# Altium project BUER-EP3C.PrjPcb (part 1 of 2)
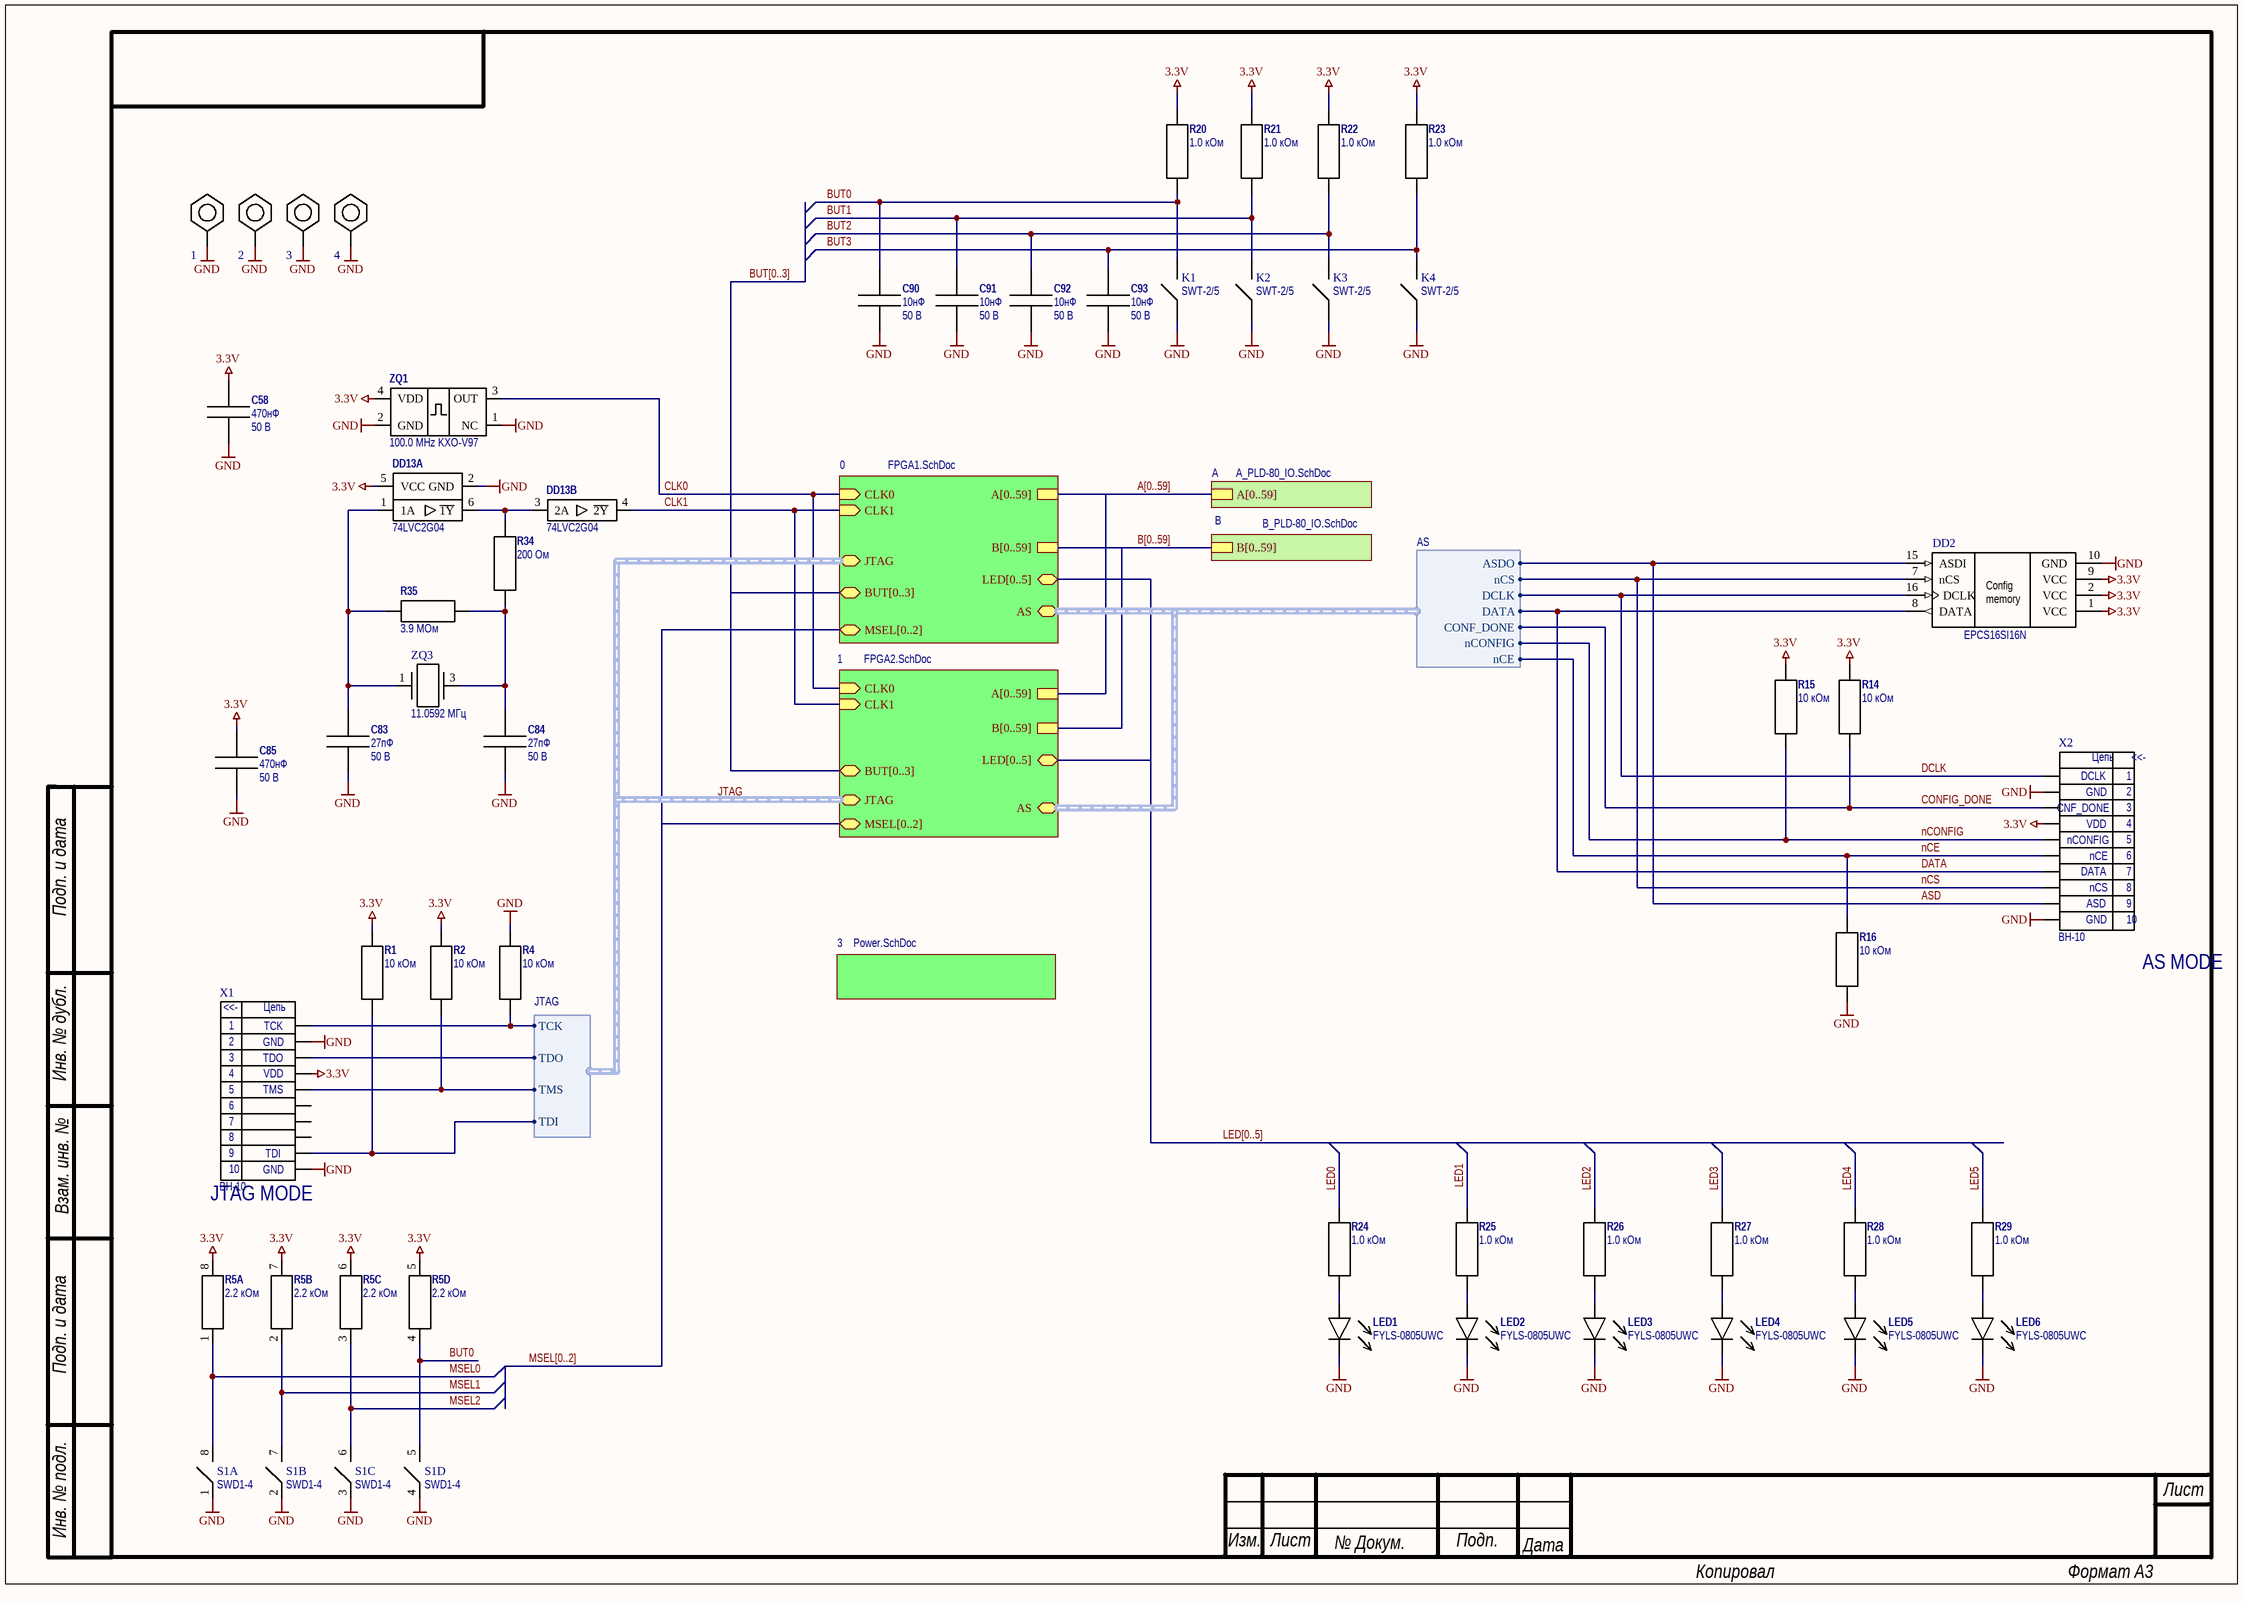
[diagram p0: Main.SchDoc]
Firma: Òåõíîèìïåêñ; Proveril: Êîñòåíêî Ì.Â; Razrabotal: Òîâñòîïÿò ß. À.; Utverdil: Áîãà÷åâ Î.Ã.
17 sheets, 295 parts. Net scope: hierarchical (ports join the sheet entries above them; power ports are global).
Board file: BUER_EP3C.PcbDoc
Sheets:
  Main.SchDoc
    0 = FPGA1.SchDoc
    3 = Power.SchDoc
      D = 5V_to_1.2V_stepdown.SchDoc
      G = 5V_to_2.5V_stepdown.SchDoc
      H = 5V_to_3.3V_stepdown.SchDoc
      S = 5A Stepdown 5V.SchDoc
      F = 5V_to_1.8V_stepdown.SchDoc
    1 = FPGA2.SchDoc
    A = A_PLD-80_IO.SchDoc
      1 = 10pin ESD protect_1.SchDoc
      2 = 10pin ESD protect_2.SchDoc
      3 = 10pin ESD protect_3.SchDoc
      4 = 10pin ESD protect_4.SchDoc
      6 = 10pin ESD protect_6.SchDoc
      5 = 10pin ESD protect_5.SchDoc
    B = B_PLD-80_IO.SchDoc
      1 = 10pin ESD protect_1.SchDoc
      2 = 10pin ESD protect_2.SchDoc
      3 = 10pin ESD protect_3.SchDoc
      4 = 10pin ESD protect_4.SchDoc
      6 = 10pin ESD protect_6.SchDoc
      5 = 10pin ESD protect_5.SchDoc

## Sheet Main.SchDoc
size custom portrait

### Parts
1  M3  [M3]  (value not drawn)
2  M3  [M3]  (value not drawn)
3  M3  [M3]  (value not drawn)
4  M3  [M3]  (value not drawn)
C58  value 470нФ  VOLTAGE: 50 В  [C0805]  (hidden comment: 470нФ 10% 50 В)
C83  value 27пФ  VOLTAGE: 50 В  [C0805]  (hidden comment: 27пФ  5%  50В 0805 NPO)
C84  value 27пФ  VOLTAGE: 50 В  [C0805]  (hidden comment: 27пФ  5%  50В 0805 NPO)
C85  value 470нФ  VOLTAGE: 50 В  [C0805]  (hidden comment: 470нФ 10% 50 В)
C90  value 10нФ  VOLTAGE: 50 В  [C0805]  (hidden comment: 10нФ 10% 50 В)
C91  value 10нФ  VOLTAGE: 50 В  [C0805]  (hidden comment: 10нФ 10% 50 В)
C92  value 10нФ  VOLTAGE: 50 В  [C0805]  (hidden comment: 10нФ 10% 50 В)
C93  value 10нФ  VOLTAGE: 50 В  [C0805]  (hidden comment: 10нФ 10% 50 В)
DD2  EPCS16SI16N  [SO-16W]
DD13  74LVC2G04  [SOT-23-6]  (parts A,B of 2)
K1  SWT-2/5 (0650HIM-160G-G)  [SWT-2/5]  (value not drawn)
K2  SWT-2/5 (0650HIM-160G-G)  [SWT-2/5]  (value not drawn)
K3  SWT-2/5 (0650HIM-160G-G)  [SWT-2/5]  (value not drawn)
K4  SWT-2/5 (0650HIM-160G-G)  [SWT-2/5]  (value not drawn)
LED1  FYLS-0805UWC  [LED0805W]
LED2  FYLS-0805UWC  [LED0805W]
LED3  FYLS-0805UWC  [LED0805W]
LED4  FYLS-0805UWC  [LED0805W]
LED5  FYLS-0805UWC  [LED0805W]
LED6  FYLS-0805UWC  [LED0805W]
R1  value 10 кОм  [R0603]  (hidden comment: 10 кОм 0603 5%)
R2  value 10 кОм  [R0603]  (hidden comment: 10 кОм 0603 5%)
R4  value 10 кОм  [R0603]  (hidden comment: 10 кОм 0603 5%)
R5  value 2.2 кОм  [4D03]  (hidden comment: 2.2 кОм 4D03)  (parts A,B,C,D of 4)
R14  value 10 кОм  [R0603]  (hidden comment: 10 кОм 0603 5%)
R15  value 10 кОм  [R0603]  (hidden comment: 10 кОм 0603 5%)
R16  value 10 кОм  [R0603]  (hidden comment: 10 кОм 0603 5%)
R20  value 1.0 кОм  [R0603]  (hidden comment: 1.0 кОм 0603 5%)
R21  value 1.0 кОм  [R0603]  (hidden comment: 1.0 кОм 0603 5%)
R22  value 1.0 кОм  [R0603]  (hidden comment: 1.0 кОм 0603 5%)
R23  value 1.0 кОм  [R0603]  (hidden comment: 1.0 кОм 0603 5%)
R24  value 1.0 кОм  [R0603]  (hidden comment: 1.0 кОм 0603 5%)
R25  value 1.0 кОм  [R0603]  (hidden comment: 1.0 кОм 0603 5%)
R26  value 1.0 кОм  [R0603]  (hidden comment: 1.0 кОм 0603 5%)
R27  value 1.0 кОм  [R0603]  (hidden comment: 1.0 кОм 0603 5%)
R28  value 1.0 кОм  [R0603]  (hidden comment: 1.0 кОм 0603 5%)
R29  value 1.0 кОм  [R0603]  (hidden comment: 1.0 кОм 0603 5%)
R34  value 200 Ом  [R0805]  (hidden comment: 200 Ом 0805 5%)
R35  value 3.9 МОм  [R0805]  (hidden comment: 3.9 МОм 0805 5%)
S1  SWD1-4  [DIPSW-4]  (parts A,B,C,D of 4)
X1  BH-10  [BH-10]
X2  BH-10  [BH-10]
ZQ1  100.0 MHz KXO-V97  [KXO-97]
ZQ3  FREQUENCY: 11.0592 МГц  [KX-9A]  (hidden comment: 11.0592MHz KX-9A)

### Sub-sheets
0 = FPGA1.SchDoc: CLK0 (in), CLK1 (in), A[0..59], B[0..59], AS (harness AS), JTAG (harness JTAG), MSEL[0..2], BUT[0..3], LED[0..5]
1 = FPGA2.SchDoc: CLK0 (in), CLK1 (in), MSEL[0..2], JTAG (harness JTAG), AS (harness AS), A[0..59], B[0..59], BUT[0..3], LED[0..5]
3 = Power.SchDoc: no entries
A = A_PLD-80_IO.SchDoc: A[0..59]
B = B_PLD-80_IO.SchDoc: B[0..59]

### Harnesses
JTAG: TCK, TDO, TMS, TDI
AS: nCE, DCLK, CONF_DONE, nCONFIG, ASDO, nCS, DATA

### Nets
3.3V: C58.1 C85.1 DD2.1(VCC) DD2.2(VCC) DD2.9(VCC) DD13.5(VCC) R1.2 R2.2 R5.5 R5.6 R5.7 R5.8 R14.2 R15.2 R20.2 R21.2 R22.2 R23.2 X1.4 X2.4 ZQ1.4(VDD)
GND: 1.0 2.0 3.0 4.0 C58.2 C83.2 C84.2 C85.2 C90.2 C91.2 C92.2 C93.2 DD2.10(GND) DD13.2(GND) K1.1 K2.1 K3.1 K4.1 LED1.K LED2.K LED3.K LED4.K LED5.K LED6.K R4.2 R16.1 S1.1 S1.2 S1.3 S1.4 X1.2 X1.10 X2.2 X2.10 ZQ1.1(NC) ZQ1.2(GND)
ASD: DD2.15(ASDI) X2.9 ; sheet 0/AS.ASDO
BUT0: C90.1 K1.2 R5.4 R20.1 S1.5
BUT1: C91.1 K2.2 R21.1
BUT2: C92.1 K3.2 R22.1
BUT3: C93.1 K4.2 R23.1
CLK0: ZQ1.3(OUT) ; sheet 0/CLK0, sheet 1/CLK0
CLK1: DD13.4(~{2Y}) ; sheet 0/CLK1, sheet 1/CLK1
CONFIG_DONE: R14.1 X2.3 ; sheet 0/AS.CONF_DONE
DATA: DD2.8(DATA) X2.7 ; sheet 0/AS.DATA
DCLK: DD2.16(DCLK) X2.1 ; sheet 0/AS.DCLK
JTAG.TCK: R4.1 X1.1 ; sheet 0/JTAG.TCK
JTAG.TDI: R1.1 X1.9 ; sheet 0/JTAG.TDI
JTAG.TDO: X1.3 ; sheet 0/JTAG.TDO
JTAG.TMS: R2.1 X1.5 ; sheet 0/JTAG.TMS
LED0: R24.2
LED1: R25.2
LED2: R26.2
LED3: R27.2
LED4: R28.2
LED5: R29.2
MSEL0: R5.1 S1.8
MSEL1: R5.2 S1.7
MSEL2: R5.3 S1.6
nCE: R16.2 X2.6 ; sheet 0/AS.nCE
nCONFIG: R15.1 X2.5 ; sheet 0/AS.nCONFIG
nCS: DD2.7(nCS) X2.8 ; sheet 0/AS.nCS
NetC83_1: C83.1 DD13.1(1A) R35.1 ZQ3.1
NetC84_1: C84.1 R34.1 R35.2 ZQ3.3
NetDD13_3: DD13.3(2A) DD13.6(~{1Y}) R34.2
NetLED1_A: LED1.A R24.1
NetLED2_A: LED2.A R25.1
NetLED3_A: LED3.A R26.1
NetLED4_A: LED4.A R27.1
NetLED5_A: LED5.A R28.1
NetLED6_A: LED6.A R29.1

Not connected (* = marked no-connect by the designer): X1 6 7 8

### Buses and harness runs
bus A[0..59] = sheet 0/A[0..59] = sheet 1/A[0..59] = sheet A/A[0..59]
bus B[0..59] = sheet 0/B[0..59] = sheet 1/B[0..59] = sheet B/B[0..59]
bus BUT[0..3] = sheet 0/BUT[0..3] = sheet 1/BUT[0..3]
bus LED[0..5] = sheet 0/LED[0..5] = sheet 1/LED[0..5]
bus MSEL[0..2] = sheet 0/MSEL[0..2] = sheet 1/MSEL[0..2]
harness JTAG = sheet 0/JTAG = sheet 1/JTAG
harness sheet 0/AS = sheet 1/AS

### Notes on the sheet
- (near X2) DCLK
- (near X2) GND
- (near X2) CNF_DONE
- (near X2) nCONFIG
- (near X2) DATA
- (near X2) VDD
- (near X2) nCE
- Подп. и дата
- (near X2) ASD
- (near X2) nCS
- (near X2) AS MODE
- (near X1) TCK
- (near X1) TDO
- (near X1) GND
- (near X1) VDD
- Инв. № дубл.
- (near X1) TMS
- (near X1) JTAG MODE
- (near X1) TDI
- Взам. инв. №
- Инв. № подл.
- Лист
- Изм.
- № Докум.
- Подп.
- Дата
- Копировал
- Формат
- А3

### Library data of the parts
C58 C85 = 470нФ 50 В: конденсатор керамический SMD; Library Reference: capacitor; articul: 389
C83 C84 = 27пФ  50В: конденсатор керамический; Library Reference: capacitor; articul: 392
C90-C93 = 10нФ 50 В: конденсатор керамический SMD; articul: 398; Designator: capacitor
DD2 = EPCS16SI16N: EPCS16 Series, In-system programmable 3.3V serial configuration device, 8-Pin SOIC, 4-Megabit, Industrial Grade
DD13 = 74LVC2G04: 2-х разрядный инвертор
K1-K4 = SWT-2/5: тактовая кнопка
LED1-LED6 = FYLS-0805UWC: белый светодиод; articul: 701
R1 R2 R4 R14-R16 = 10 кОм 0603 5%: резистор постоянный; articul: 918
R5 = 2.2 кОм 4D03: Массив резисторов; Library Reference: 4X; articul: 138
R20-R29 = 1.0 кОм 0603 5%: резистор постоянный; articul: 720
R34 = 200 Ом 0805 5%: резистор постоянный; articul: 91
R35 = 3.9 МОм 0805 5%: резистор постоянный; articul: 86
S1 = SWD1-4: DIP переключатель на 4 позиции; articul: 140
X1 X2 = BH-10: вилка IDC на плату прямая; articul: 37
ZQ1 = 100.0 MHz KXO-V97: Кварцевый генератор
ZQ3 = 11.0592MHz KX-9A: Кварцевый резонатор; articul: 263

## Sheet FPGA1.SchDoc
size custom portrait
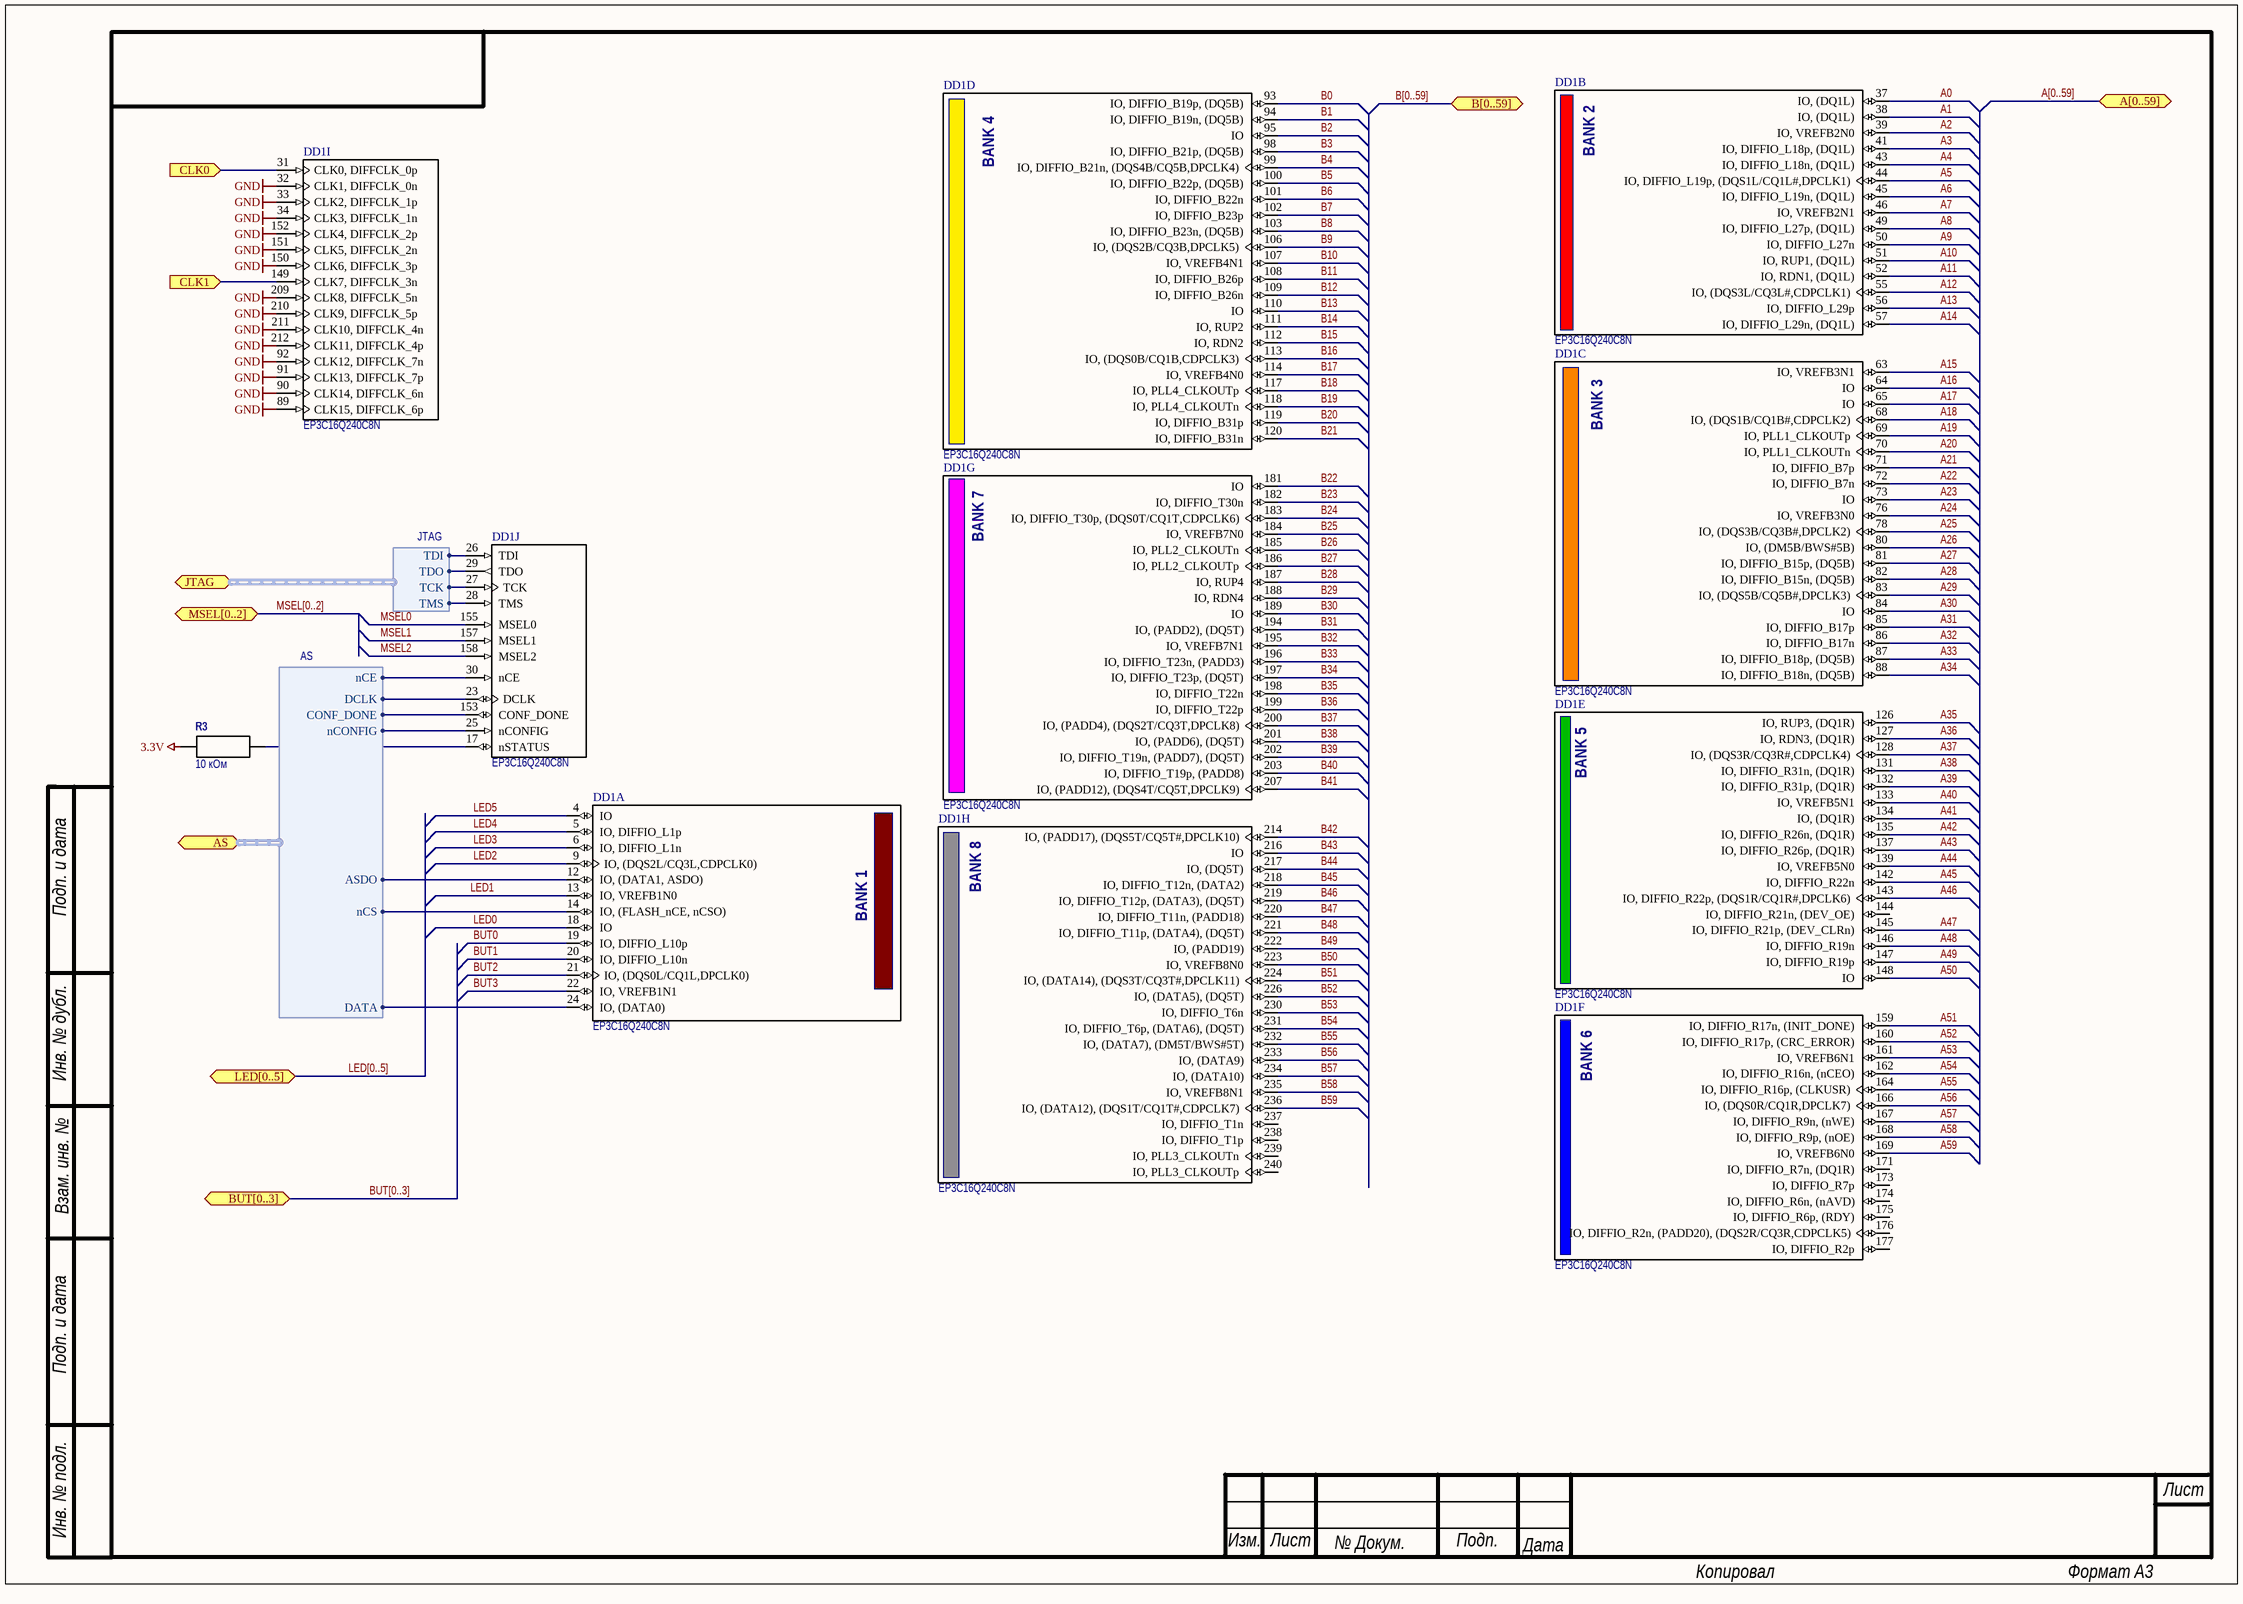
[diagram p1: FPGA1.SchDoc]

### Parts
DD1  EP3C16Q240C8N  [PQFP240_N]  (parts A,B,C,D,E,F,G,H,I,J of 13)
R3  value 10 кОм  [R0603]  (hidden comment: 10 кОм 0603 5%)

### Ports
A[0..59], AS (harness AS), B[0..59], BUT[0..3], CLK0 (in), CLK1 (in), JTAG (harness JTAG), LED[0..5], MSEL[0..2]

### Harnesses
JTAG: TCK, TDO, TMS, TDI
AS: nCE, DCLK, CONF_DONE, nCONFIG, ASDO, nCS, DATA

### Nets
3.3V: R3.2
GND: DD1.32(CLK1,_DIFFCLK_0n) DD1.33(CLK2,_DIFFCLK_1p) DD1.34(CLK3,_DIFFCLK_1n) DD1.89(CLK15,_DIFFCLK_6p) DD1.90(CLK14,_DIFFCLK_6n) DD1.91(CLK13,_DIFFCLK_7p) DD1.92(CLK12,_DIFFCLK_7n) DD1.150(CLK6,_DIFFCLK_3p) DD1.151(CLK5,_DIFFCLK_2n) DD1.152(CLK4,_DIFFCLK_2p) DD1.209(CLK8,_DIFFCLK_5n) DD1.210(CLK9,_DIFFCLK_5p) DD1.211(CLK10,_DIFFCLK_4n) DD1.212(CLK11,_DIFFCLK_4p)
A0: DD1.37(IO,_(DQ1L))
A1: DD1.38(IO,_(DQ1L))
A2: DD1.39(IO,_VREFB2N0)
A3: DD1.41(IO,_DIFFIO_L18p,_(DQ1L))
A4: DD1.43(IO,_DIFFIO_L18n,_(DQ1L))
A5: DD1.44(IO,_DIFFIO_L19p,_(DQS1L/CQ1L#,DPCLK1))
A6: DD1.45(IO,_DIFFIO_L19n,_(DQ1L))
A7: DD1.46(IO,_VREFB2N1)
A8: DD1.49(IO,_DIFFIO_L27p,_(DQ1L))
A9: DD1.50(IO,_DIFFIO_L27n)
A10: DD1.51(IO,_RUP1,_(DQ1L))
A11: DD1.52(IO,_RDN1,_(DQ1L))
A12: DD1.55(IO,_(DQS3L/CQ3L#,CDPCLK1))
A13: DD1.56(IO,_DIFFIO_L29p)
A14: DD1.57(IO,_DIFFIO_L29n,_(DQ1L))
A15: DD1.63(IO,_VREFB3N1)
A16: DD1.64(IO)
A17: DD1.65(IO)
A18: DD1.68(IO,_(DQS1B/CQ1B#,CDPCLK2))
A19: DD1.69(IO,_PLL1_CLKOUTp)
A20: DD1.70(IO,_PLL1_CLKOUTn)
A21: DD1.71(IO,_DIFFIO_B7p)
A22: DD1.72(IO,_DIFFIO_B7n)
A23: DD1.73(IO)
A24: DD1.76(IO,_VREFB3N0)
A25: DD1.78(IO,_(DQS3B/CQ3B#,DPCLK2))
A26: DD1.80(IO,_(DM5B/BWS#5B))
A27: DD1.81(IO,_DIFFIO_B15p,_(DQ5B))
A28: DD1.82(IO,_DIFFIO_B15n,_(DQ5B))
A29: DD1.83(IO,_(DQS5B/CQ5B#,DPCLK3))
A30: DD1.84(IO)
A31: DD1.85(IO,_DIFFIO_B17p)
A32: DD1.86(IO,_DIFFIO_B17n)
A33: DD1.87(IO,_DIFFIO_B18p,_(DQ5B))
A34: DD1.88(IO,_DIFFIO_B18n,_(DQ5B))
A35: DD1.126(IO,_RUP3,_(DQ1R))
A36: DD1.127(IO,_RDN3,_(DQ1R))
A37: DD1.128(IO,_(DQS3R/CQ3R#,CDPCLK4))
A38: DD1.131(IO,_DIFFIO_R31n,_(DQ1R))
A39: DD1.132(IO,_DIFFIO_R31p,_(DQ1R))
A40: DD1.133(IO,_VREFB5N1)
A41: DD1.134(IO,_(DQ1R))
A42: DD1.135(IO,_DIFFIO_R26n,_(DQ1R))
A43: DD1.137(IO,_DIFFIO_R26p,_(DQ1R))
A44: DD1.139(IO,_VREFB5N0)
A45: DD1.142(IO,_DIFFIO_R22n)
A46: DD1.143(IO,_DIFFIO_R22p,_(DQS1R/CQ1R#,DPCLK6))
A47: DD1.145(IO,_DIFFIO_R21p,_(DEV_CLRn))
A48: DD1.146(IO,_DIFFIO_R19n)
A49: DD1.147(IO,_DIFFIO_R19p)
A50: DD1.148(IO)
A51: DD1.159(IO,_DIFFIO_R17n,_(INIT_DONE))
A52: DD1.160(IO,_DIFFIO_R17p,_(CRC_ERROR))
A53: DD1.161(IO,_VREFB6N1)
A54: DD1.162(IO,_DIFFIO_R16n,_(nCEO))
A55: DD1.164(IO,_DIFFIO_R16p,_(CLKUSR))
A56: DD1.166(IO,_(DQS0R/CQ1R,DPCLK7))
A57: DD1.167(IO,_DIFFIO_R9n,_(nWE))
A58: DD1.168(IO,_DIFFIO_R9p,_(nOE))
A59: DD1.169(IO,_VREFB6N0)
ASD: DD1.12(IO,_(DATA1,_ASDO)) ; port AS.ASDO
B0: DD1.93(IO,_DIFFIO_B19p,_(DQ5B))
B1: DD1.94(IO,_DIFFIO_B19n,_(DQ5B))
B2: DD1.95(IO)
B3: DD1.98(IO,_DIFFIO_B21p,_(DQ5B))
B4: DD1.99(IO,_DIFFIO_B21n,_(DQS4B/CQ5B,DPCLK4))
B5: DD1.100(IO,_DIFFIO_B22p,_(DQ5B))
B6: DD1.101(IO,_DIFFIO_B22n)
B7: DD1.102(IO,_DIFFIO_B23p)
B8: DD1.103(IO,_DIFFIO_B23n,_(DQ5B))
B9: DD1.106(IO,_(DQS2B/CQ3B,DPCLK5))
B10: DD1.107(IO,_VREFB4N1)
B11: DD1.108(IO,_DIFFIO_B26p)
B12: DD1.109(IO,_DIFFIO_B26n)
B13: DD1.110(IO)
B14: DD1.111(IO,_RUP2)
B15: DD1.112(IO,_RDN2)
B16: DD1.113(IO,_(DQS0B/CQ1B,CDPCLK3))
B17: DD1.114(IO,_VREFB4N0)
B18: DD1.117(IO,_PLL4_CLKOUTp)
B19: DD1.118(IO,_PLL4_CLKOUTn)
B20: DD1.119(IO,_DIFFIO_B31p)
B21: DD1.120(IO,_DIFFIO_B31n)
B22: DD1.181(IO)
B23: DD1.182(IO,_DIFFIO_T30n)
B24: DD1.183(IO,_DIFFIO_T30p,_(DQS0T/CQ1T,CDPCLK6))
B25: DD1.184(IO,_VREFB7N0)
B26: DD1.185(IO,_PLL2_CLKOUTn)
B27: DD1.186(IO,_PLL2_CLKOUTp)
B28: DD1.187(IO,_RUP4)
B29: DD1.188(IO,_RDN4)
B30: DD1.189(IO)
B31: DD1.194(IO,_(PADD2),_(DQ5T))
B32: DD1.195(IO,_VREFB7N1)
B33: DD1.196(IO,_DIFFIO_T23n,_(PADD3))
B34: DD1.197(IO,_DIFFIO_T23p,_(DQ5T))
B35: DD1.198(IO,_DIFFIO_T22n)
B36: DD1.199(IO,_DIFFIO_T22p)
B37: DD1.200(IO,_(PADD4),_(DQS2T/CQ3T,DPCLK8))
B38: DD1.201(IO,_(PADD6),_(DQ5T))
B39: DD1.202(IO,_DIFFIO_T19n,_(PADD7),_(DQ5T))
B40: DD1.203(IO,_DIFFIO_T19p,_(PADD8))
B41: DD1.207(IO,_(PADD12),_(DQS4T/CQ5T,DPCLK9))
B42: DD1.214(IO,_(PADD17),_(DQS5T/CQ5T#,DPCLK10))
B43: DD1.216(IO)
B44: DD1.217(IO,_(DQ5T))
B45: DD1.218(IO,_DIFFIO_T12n,_(DATA2))
B46: DD1.219(IO,_DIFFIO_T12p,_(DATA3),_(DQ5T))
B47: DD1.220(IO,_DIFFIO_T11n,_(PADD18))
B48: DD1.221(IO,_DIFFIO_T11p,_(DATA4),_(DQ5T))
B49: DD1.222(IO,_(PADD19))
B50: DD1.223(IO,_VREFB8N0)
B51: DD1.224(IO,_(DATA14),_(DQS3T/CQ3T#,DPCLK11))
B52: DD1.226(IO,_(DATA5),_(DQ5T))
B53: DD1.230(IO,_DIFFIO_T6n)
B54: DD1.231(IO,_DIFFIO_T6p,_(DATA6),_(DQ5T))
B55: DD1.232(IO,_(DATA7),_(DM5T/BWS#5T))
B56: DD1.233(IO,_(DATA9))
B57: DD1.234(IO,_(DATA10))
B58: DD1.235(IO,_VREFB8N1)
B59: DD1.236(IO,_(DATA12),_(DQS1T/CQ1T#,CDPCLK7))
BUT0: DD1.19(IO,_DIFFIO_L10p)
BUT1: DD1.20(IO,_DIFFIO_L10n)
BUT2: DD1.21(IO,_(DQS0L/CQ1L,DPCLK0))
BUT3: DD1.22(IO,_VREFB1N1)
CLK0: DD1.31(CLK0,_DIFFCLK_0p) ; port CLK0
CLK1: DD1.149(CLK7,_DIFFCLK_3n) ; port CLK1
CONFIG_DONE: DD1.153(CONF_DONE) ; port AS.CONF_DONE
DATA: DD1.24(IO,_(DATA0)) ; port AS.DATA
DCLK: DD1.23(DCLK) ; port AS.DCLK
JTAG.TCK: DD1.27(TCK) ; port JTAG.TCK
JTAG.TDI: DD1.26(TDI) ; port JTAG.TDI
JTAG.TDO: DD1.29(TDO) ; port JTAG.TDO
JTAG.TMS: DD1.28(TMS) ; port JTAG.TMS
LED0: DD1.18(IO)
LED1: DD1.13(IO,_VREFB1N0)
LED2: DD1.9(IO,_(DQS2L/CQ3L,CDPCLK0))
LED3: DD1.6(IO,_DIFFIO_L1n)
LED4: DD1.5(IO,_DIFFIO_L1p)
LED5: DD1.4(IO)
MSEL0: DD1.155(MSEL0)
MSEL1: DD1.157(MSEL1)
MSEL2: DD1.158(MSEL2)
nCE: DD1.30(nCE) ; port AS.nCE
nCONFIG: DD1.25(nCONFIG) ; port AS.nCONFIG
nCS: DD1.14(IO,_(FLASH_nCE,_nCSO)) ; port AS.nCS
NetDD1_17: DD1.17(nSTATUS) R3.1

Not connected (* = marked no-connect by the designer): DD1 144(IO,_DIFFIO_R21n,_(DEV_OE)) 171(IO,_DIFFIO_R7n,_(DQ1R)) 173(IO,_DIFFIO_R7p) 174(IO,_DIFFIO_R6n,_(nAVD)) 175(IO,_DIFFIO_R6p,_(RDY)) 176(IO,_DIFFIO_R2n,_(PADD20),_(DQS2R/CQ3R,CDPCLK5)) 177(IO,_DIFFIO_R2p) 237(IO,_DIFFIO_T1n) 238(IO,_DIFFIO_T1p) 239(IO,_PLL3_CLKOUTn) 240(IO,_PLL3_CLKOUTp)

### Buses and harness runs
bus A[0..59] = port A[0..59]
bus B[0..59] = port B[0..59]
bus BUT[0..3] = port BUT[0..3]
bus LED[0..5] = port LED[0..5]
bus MSEL[0..2] = port MSEL[0..2]

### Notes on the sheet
- Подп. и дата
- Инв. № дубл.
- Взам. инв. №
- Инв. № подл.
- Лист
- Изм.
- № Докум.
- Подп.
- Дата
- Копировал
- Формат
- А3

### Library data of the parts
DD1 = EP3C16Q240C8N: Cyclone III Family FPGA, 160 I/O Pins, 4 PLLs, 240-Pin PQFP, Speed Grade 8, Commercial Grade, Pb-Free
R3 = 10 кОм 0603 5%: резистор постоянный; articul: 918

## Sheet Power.SchDoc
size custom portrait
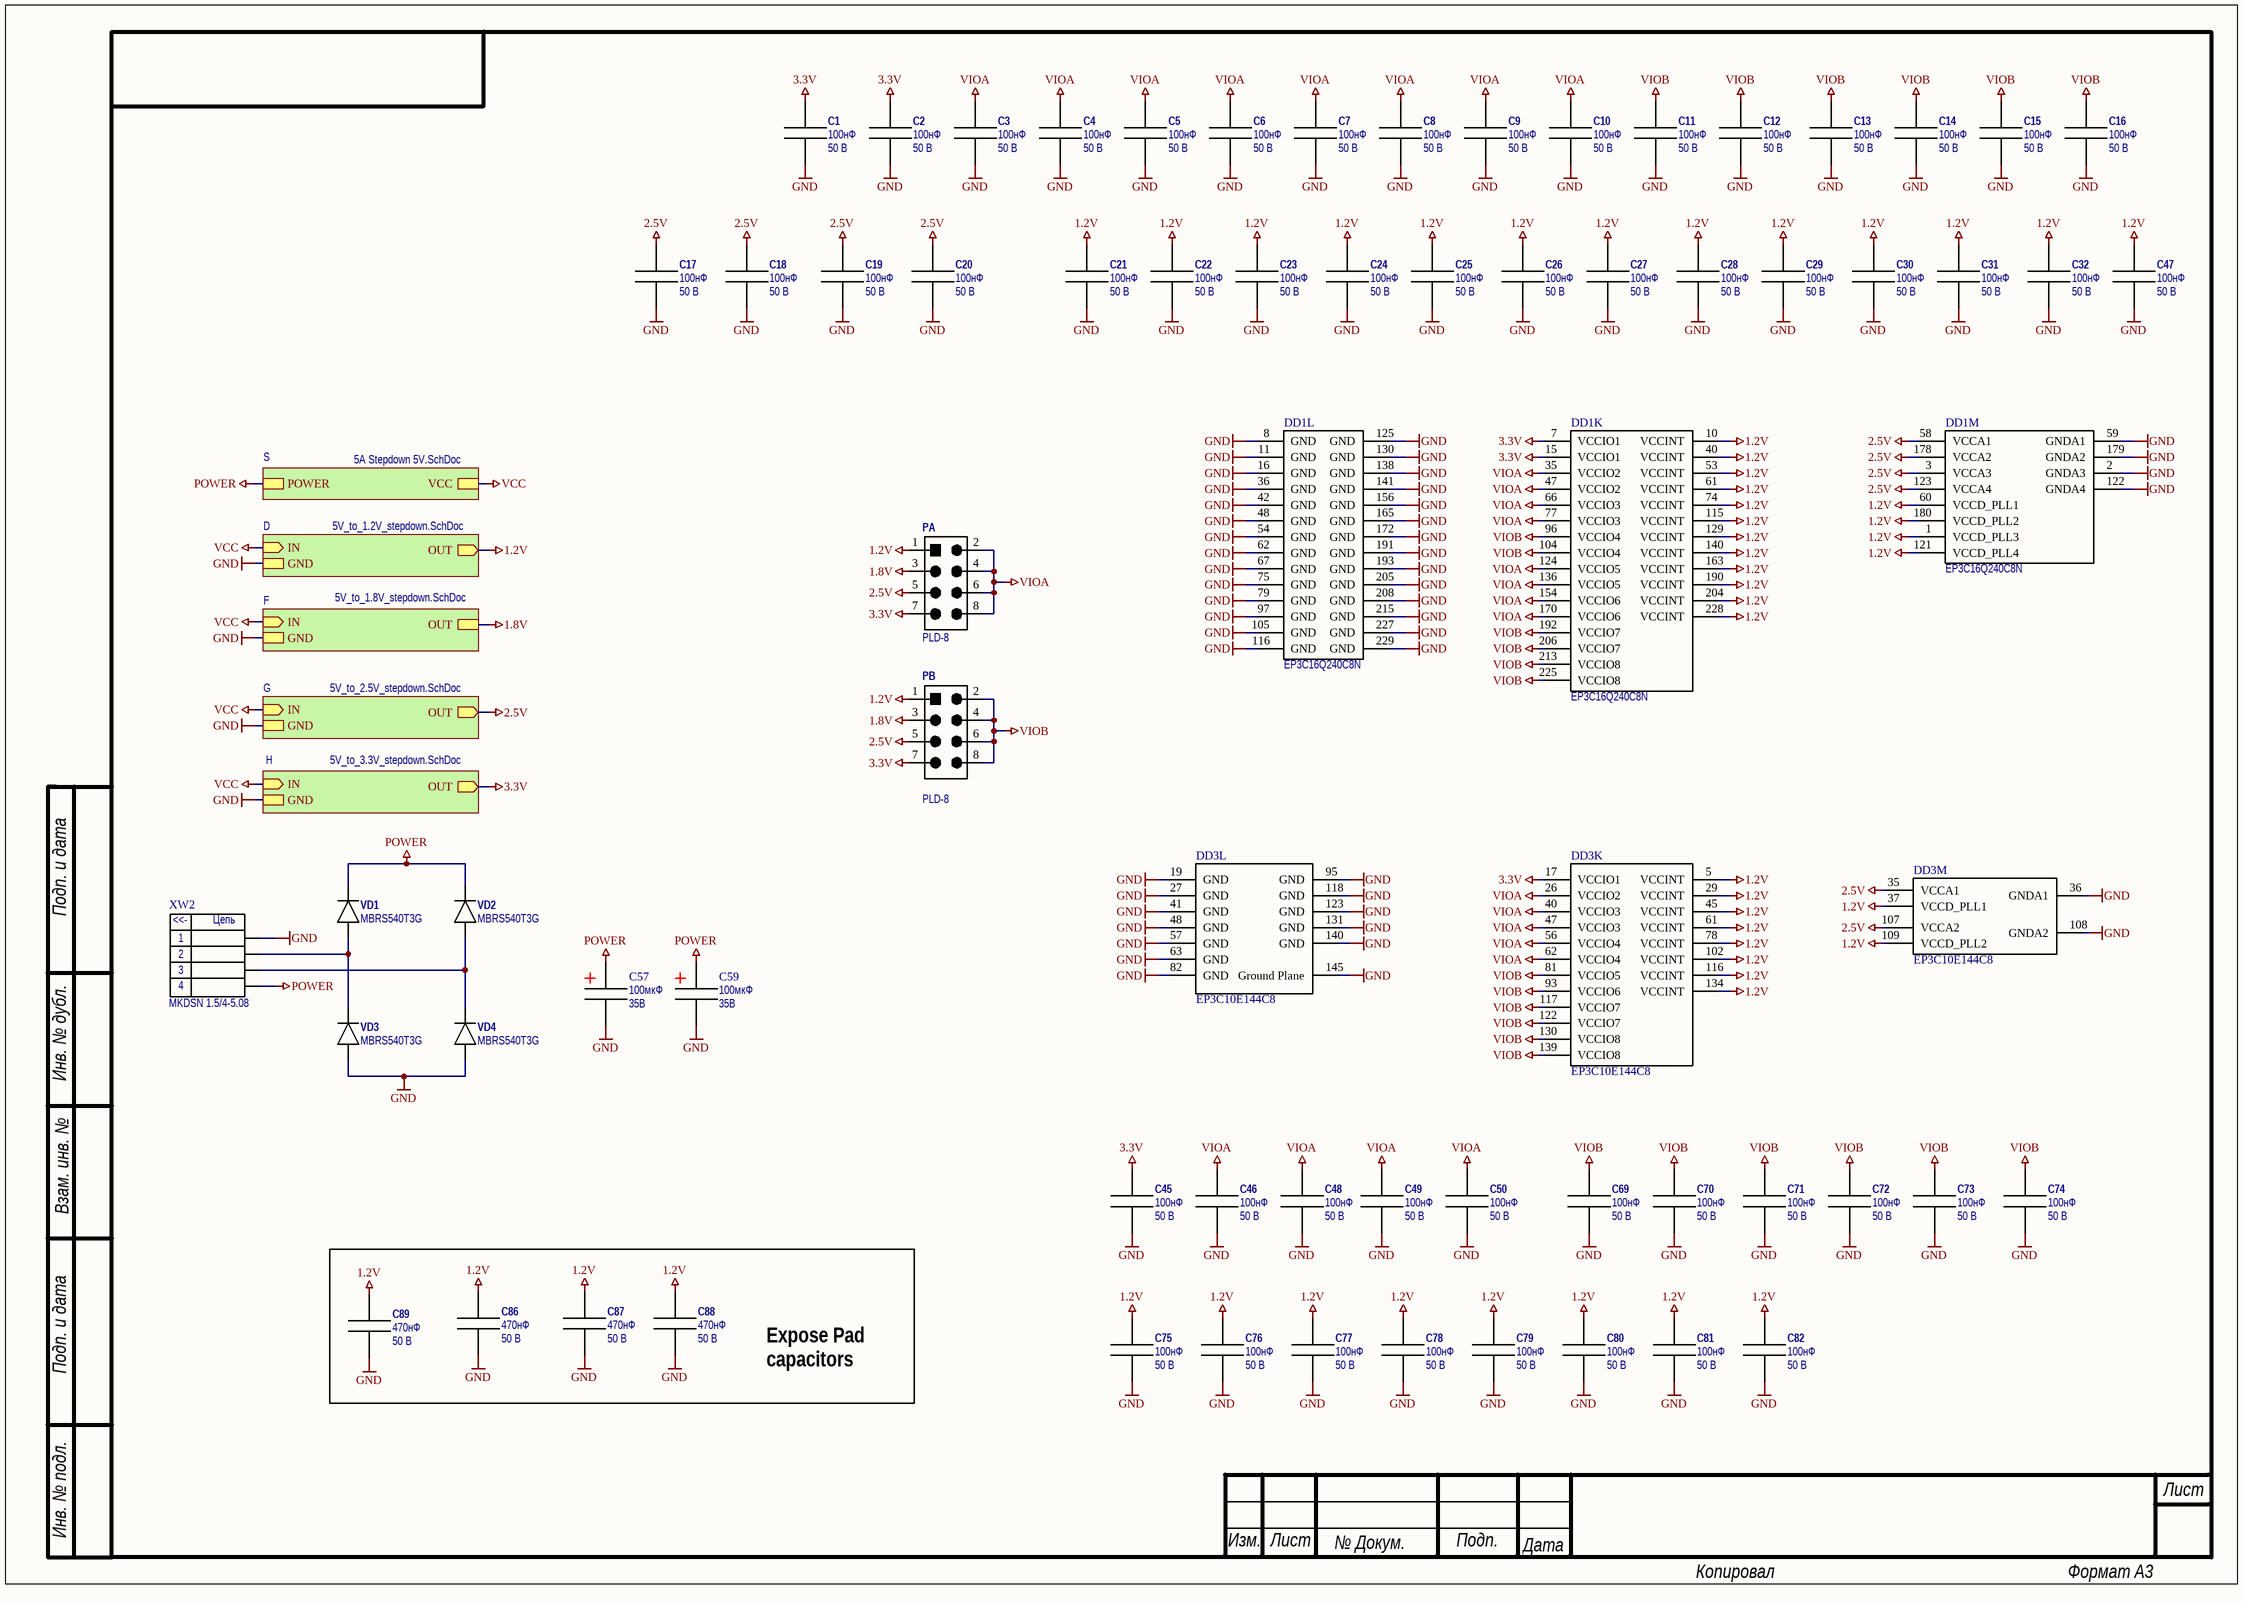
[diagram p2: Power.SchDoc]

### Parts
C1  value 100нФ  VOLTAGE: 50 В  [C0603]  (hidden comment: 100нФ 50 В 10% 0603 X7R)
C2  value 100нФ  VOLTAGE: 50 В  [C0603]  (hidden comment: 100нФ 50 В 10% 0603 X7R)
C3  value 100нФ  VOLTAGE: 50 В  [C0603]  (hidden comment: 100нФ 50 В 10% 0603 X7R)
C4  value 100нФ  VOLTAGE: 50 В  [C0603]  (hidden comment: 100нФ 50 В 10% 0603 X7R)
C5  value 100нФ  VOLTAGE: 50 В  [C0603]  (hidden comment: 100нФ 50 В 10% 0603 X7R)
C6  value 100нФ  VOLTAGE: 50 В  [C0603]  (hidden comment: 100нФ 50 В 10% 0603 X7R)
C7  value 100нФ  VOLTAGE: 50 В  [C0603]  (hidden comment: 100нФ 50 В 10% 0603 X7R)
C8  value 100нФ  VOLTAGE: 50 В  [C0603]  (hidden comment: 100нФ 50 В 10% 0603 X7R)
C9  value 100нФ  VOLTAGE: 50 В  [C0603]  (hidden comment: 100нФ 50 В 10% 0603 X7R)
C10  value 100нФ  VOLTAGE: 50 В  [C0603]  (hidden comment: 100нФ 50 В 10% 0603 X7R)
C11  value 100нФ  VOLTAGE: 50 В  [C0603]  (hidden comment: 100нФ 50 В 10% 0603 X7R)
C12  value 100нФ  VOLTAGE: 50 В  [C0603]  (hidden comment: 100нФ 50 В 10% 0603 X7R)
C13  value 100нФ  VOLTAGE: 50 В  [C0603]  (hidden comment: 100нФ 50 В 10% 0603 X7R)
C14  value 100нФ  VOLTAGE: 50 В  [C0603]  (hidden comment: 100нФ 50 В 10% 0603 X7R)
C15  value 100нФ  VOLTAGE: 50 В  [C0603]  (hidden comment: 100нФ 50 В 10% 0603 X7R)
C16  value 100нФ  VOLTAGE: 50 В  [C0603]  (hidden comment: 100нФ 50 В 10% 0603 X7R)
C17  value 100нФ  VOLTAGE: 50 В  [C0603]  (hidden comment: 100нФ 50 В 10% 0603 X7R)
C18  value 100нФ  VOLTAGE: 50 В  [C0603]  (hidden comment: 100нФ 50 В 10% 0603 X7R)
C19  value 100нФ  VOLTAGE: 50 В  [C0603]  (hidden comment: 100нФ 50 В 10% 0603 X7R)
C20  value 100нФ  VOLTAGE: 50 В  [C0603]  (hidden comment: 100нФ 50 В 10% 0603 X7R)
C21  value 100нФ  VOLTAGE: 50 В  [C0603]  (hidden comment: 100нФ 50 В 10% 0603 X7R)
C22  value 100нФ  VOLTAGE: 50 В  [C0603]  (hidden comment: 100нФ 50 В 10% 0603 X7R)
C23  value 100нФ  VOLTAGE: 50 В  [C0603]  (hidden comment: 100нФ 50 В 10% 0603 X7R)
C24  value 100нФ  VOLTAGE: 50 В  [C0603]  (hidden comment: 100нФ 50 В 10% 0603 X7R)
C25  value 100нФ  VOLTAGE: 50 В  [C0603]  (hidden comment: 100нФ 50 В 10% 0603 X7R)
C26  value 100нФ  VOLTAGE: 50 В  [C0603]  (hidden comment: 100нФ 50 В 10% 0603 X7R)
C27  value 100нФ  VOLTAGE: 50 В  [C0603]  (hidden comment: 100нФ 50 В 10% 0603 X7R)
C28  value 100нФ  VOLTAGE: 50 В  [C0603]  (hidden comment: 100нФ 50 В 10% 0603 X7R)
C29  value 100нФ  VOLTAGE: 50 В  [C0603]  (hidden comment: 100нФ 50 В 10% 0603 X7R)
C30  value 100нФ  VOLTAGE: 50 В  [C0603]  (hidden comment: 100нФ 50 В 10% 0603 X7R)
C31  value 100нФ  VOLTAGE: 50 В  [C0603]  (hidden comment: 100нФ 50 В 10% 0603 X7R)
C32  value 100нФ  VOLTAGE: 50 В  [C0603]  (hidden comment: 100нФ 50 В 10% 0603 X7R)
C45  value 100нФ  VOLTAGE: 50 В  [C0603]  (hidden comment: 100нФ 50 В 10% 0603 X7R)
C46  value 100нФ  VOLTAGE: 50 В  [C0603]  (hidden comment: 100нФ 50 В 10% 0603 X7R)
C47  value 100нФ  VOLTAGE: 50 В  [C0603]  (hidden comment: 100нФ 50 В 10% 0603 X7R)
C48  value 100нФ  VOLTAGE: 50 В  [C0603]  (hidden comment: 100нФ 50 В 10% 0603 X7R)
C49  value 100нФ  VOLTAGE: 50 В  [C0603]  (hidden comment: 100нФ 50 В 10% 0603 X7R)
C50  value 100нФ  VOLTAGE: 50 В  [C0603]  (hidden comment: 100нФ 50 В 10% 0603 X7R)
C57  value 100мкФ  VOLTAGE: 35В  [ELCAP_SMD_6.3x8]  (hidden comment: 100мкФ 35В 6.3x8)
C59  value 100мкФ  VOLTAGE: 35В  [ELCAP_SMD_6.3x8]  (hidden comment: 100мкФ 35В 6.3x8)
C69  value 100нФ  VOLTAGE: 50 В  [C0603]  (hidden comment: 100нФ 50 В 10% 0603 X7R)
C70  value 100нФ  VOLTAGE: 50 В  [C0603]  (hidden comment: 100нФ 50 В 10% 0603 X7R)
C71  value 100нФ  VOLTAGE: 50 В  [C0603]  (hidden comment: 100нФ 50 В 10% 0603 X7R)
C72  value 100нФ  VOLTAGE: 50 В  [C0603]  (hidden comment: 100нФ 50 В 10% 0603 X7R)
C73  value 100нФ  VOLTAGE: 50 В  [C0603]  (hidden comment: 100нФ 50 В 10% 0603 X7R)
C74  value 100нФ  VOLTAGE: 50 В  [C0603]  (hidden comment: 100нФ 50 В 10% 0603 X7R)
C75  value 100нФ  VOLTAGE: 50 В  [C0603]  (hidden comment: 100нФ 50 В 10% 0603 X7R)
C76  value 100нФ  VOLTAGE: 50 В  [C0603]  (hidden comment: 100нФ 50 В 10% 0603 X7R)
C77  value 100нФ  VOLTAGE: 50 В  [C0603]  (hidden comment: 100нФ 50 В 10% 0603 X7R)
C78  value 100нФ  VOLTAGE: 50 В  [C0603]  (hidden comment: 100нФ 50 В 10% 0603 X7R)
C79  value 100нФ  VOLTAGE: 50 В  [C0603]  (hidden comment: 100нФ 50 В 10% 0603 X7R)
C80  value 100нФ  VOLTAGE: 50 В  [C0603]  (hidden comment: 100нФ 50 В 10% 0603 X7R)
C81  value 100нФ  VOLTAGE: 50 В  [C0603]  (hidden comment: 100нФ 50 В 10% 0603 X7R)
C82  value 100нФ  VOLTAGE: 50 В  [C0603]  (hidden comment: 100нФ 50 В 10% 0603 X7R)
C86  value 470нФ  VOLTAGE: 50 В  [C0805]  (hidden comment: 470нФ 10% 50 В)
C87  value 470нФ  VOLTAGE: 50 В  [C0805]  (hidden comment: 470нФ 10% 50 В)
C88  value 470нФ  VOLTAGE: 50 В  [C0805]  (hidden comment: 470нФ 10% 50 В)
C89  value 470нФ  VOLTAGE: 50 В  [C0805]  (hidden comment: 470нФ 10% 50 В)
DD1  EP3C16Q240C8N  [PQFP240_N]  (parts K,L,M of 13)
DD3  EP3C10E144C8  [EQFP-144]  (parts K,L,M of 13)
PA  PLD-8  [HEADER 2X4]
PB  PLD-8  [HEADER 2X4]
VD1  MBRS540T3G  [DO-214AB (SMC)]
VD2  MBRS540T3G  [DO-214AB (SMC)]
VD3  MBRS540T3G  [DO-214AB (SMC)]
VD4  MBRS540T3G  [DO-214AB (SMC)]
XW2  MKDSN 1.5/4-5.08  [MKDSN 1.5/4-5.08]

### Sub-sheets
D = 5V_to_1.2V_stepdown.SchDoc: IN (in), OUT, GND
F = 5V_to_1.8V_stepdown.SchDoc: IN (in), OUT, GND
G = 5V_to_2.5V_stepdown.SchDoc: IN (in), OUT, GND
H = 5V_to_3.3V_stepdown.SchDoc: IN (in), OUT, GND
S = 5A Stepdown 5V.SchDoc: VCC, POWER

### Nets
1.2V: C21.1 C22.1 C23.1 C24.1 C25.1 C26.1 C27.1 C28.1 C29.1 C30.1 C31.1 C32.1 C47.1 C75.1 C76.1 C77.1 C78.1 C79.1 C80.1 C81.1 C82.1 C86.1 C87.1 C88.1 C89.1 DD1.1(VCCD_PLL3) DD1.10(VCCINT) DD1.40(VCCINT) DD1.53(VCCINT) DD1.60(VCCD_PLL1) DD1.61(VCCINT) DD1.74(VCCINT) DD1.115(VCCINT) DD1.121(VCCD_PLL4) DD1.129(VCCINT) DD1.140(VCCINT) DD1.163(VCCINT) DD1.180(VCCD_PLL2) DD1.190(VCCINT) DD1.204(VCCINT) DD1.228(VCCINT) DD3.5(VCCINT) DD3.29(VCCINT) DD3.37(VCCD_PLL1) DD3.45(VCCINT) DD3.61(VCCINT) DD3.78(VCCINT) DD3.102(VCCINT) DD3.109(VCCD_PLL2) DD3.116(VCCINT) DD3.134(VCCINT) PA.1 PB.1 ; sheet D/OUT
1.8V: PA.3 PB.3 ; sheet F/OUT
2.5V: C17.1 C18.1 C19.1 C20.1 DD1.3(VCCA3) DD1.58(VCCA1) DD1.123(VCCA4) DD1.178(VCCA2) DD3.35(VCCA1) DD3.107(VCCA2) PA.5 PB.5 ; sheet G/OUT
3.3V: C1.1 C2.1 C45.1 DD1.7(VCCIO1) DD1.15(VCCIO1) DD3.17(VCCIO1) PA.7 PB.7 ; sheet H/OUT
GND: C1.2 C2.2 C3.2 C4.2 C5.2 C6.2 C7.2 C8.2 C9.2 C10.2 C11.2 C12.2 C13.2 C14.2 C15.2 C16.2 C17.2 C18.2 C19.2 C20.2 C21.2 C22.2 C23.2 C24.2 C25.2 C26.2 C27.2 C28.2 C29.2 C30.2 C31.2 C32.2 C45.2 C46.2 C47.2 C48.2 C49.2 C50.2 C57.2 C59.2 C69.2 C70.2 C71.2 C72.2 C73.2 C74.2 C75.2 C76.2 C77.2 C78.2 C79.2 C80.2 C81.2 C82.2 C86.2 C87.2 C88.2 C89.2 DD1.2(GNDA3) DD1.8(GND) DD1.11(GND) DD1.16(GND) DD1.36(GND) DD1.42(GND) DD1.48(GND) DD1.54(GND) DD1.59(GNDA1) DD1.62(GND) DD1.67(GND) DD1.75(GND) DD1.79(GND) DD1.97(GND) DD1.105(GND) DD1.116(GND) DD1.122(GNDA4) DD1.125(GND) DD1.130(GND) DD1.138(GND) DD1.141(GND) DD1.156(GND) DD1.165(GND) DD1.172(GND) DD1.179(GNDA2) DD1.191(GND) DD1.193(GND) DD1.205(GND) DD1.208(GND) DD1.215(GND) DD1.227(GND) DD1.229(GND) DD3.19(GND) DD3.27(GND) DD3.36(GNDA1) DD3.41(GND) DD3.48(GND) DD3.57(GND) DD3.63(GND) DD3.82(GND) DD3.95(GND) DD3.108(GNDA2) DD3.118(GND) DD3.123(GND) DD3.131(GND) DD3.140(GND) DD3.145(Ground_Plane) VD3.1 VD4.1 XW2.1 ; sheet D/GND, sheet G/GND, sheet H/GND, sheet F/GND
POWER: C57.1 C59.1 VD1.2 VD2.2 XW2.4 ; sheet S/POWER
VCC: sheet D/IN, sheet G/IN, sheet H/IN, sheet S/VCC, sheet F/IN
VIOA: C3.1 C4.1 C5.1 C6.1 C7.1 C8.1 C9.1 C10.1 C46.1 C48.1 C49.1 C50.1 DD1.35(VCCIO2) DD1.47(VCCIO2) DD1.66(VCCIO3) DD1.77(VCCIO3) DD1.124(VCCIO5) DD1.136(VCCIO5) DD1.154(VCCIO6) DD1.170(VCCIO6) DD3.26(VCCIO2) DD3.40(VCCIO3) DD3.47(VCCIO3) DD3.56(VCCIO4) DD3.62(VCCIO4) PA.2 PA.4 PA.6 PA.8
VIOB: C11.1 C12.1 C13.1 C14.1 C15.1 C16.1 C69.1 C70.1 C71.1 C72.1 C73.1 C74.1 DD1.96(VCCIO4) DD1.104(VCCIO4) DD1.192(VCCIO7) DD1.206(VCCIO7) DD1.213(VCCIO8) DD1.225(VCCIO8) DD3.81(VCCIO5) DD3.93(VCCIO6) DD3.117(VCCIO7) DD3.122(VCCIO7) DD3.130(VCCIO8) DD3.139(VCCIO8) PB.2 PB.4 PB.6 PB.8
NetVD1_1: VD1.1 VD3.2 XW2.2
NetVD2_1: VD2.1 VD4.2 XW2.3

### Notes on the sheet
- Подп. и дата
- Инв. № дубл.
- Взам. инв. №
- Expose Pad
  capacitors
- Инв. № подл.
- Лист
- Изм.
- № Докум.
- Подп.
- Дата
- Копировал
- Формат
- А3

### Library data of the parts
C1-C32 C45-C50 C69-C82 = 100нФ 50 В: конденсатор керамический SMD; articul: 949; Designator: capacitor
C57 C59 = 100мкФ 35В 6.3x8: конденсатор электролитический SMD; Library Reference: CAP; articul: 617
C86-C89 = 470нФ 50 В: конденсатор керамический SMD; articul: 389; Designator: capacitor
DD1 = EP3C16Q240C8N: as DD1 on sheet FPGA1
DD3 = EP3C10E144C8: Cyclone III Family FPGA, 94 I/O Pins, 4 PLLs, 144-Pin EQFP, Speed Grade 8, Commercial Grade; Note: Exposed pad at the bottom of this package must be connected to PCB GND.
PA PB = PLD-8: Штырьки на плату шаг 2,54 мм
VD1-VD4 = MBRS540T3G: High-Current Density Schottky Rectifier; If: 5A; Vbr: 40V; Vf: 0.5V; VENDOR: VISHAY
XW2 = MKDSN 1.5/4-5.08: articul: 797

## Sheet 5V_to_1.2V_stepdown.SchDoc
size A4
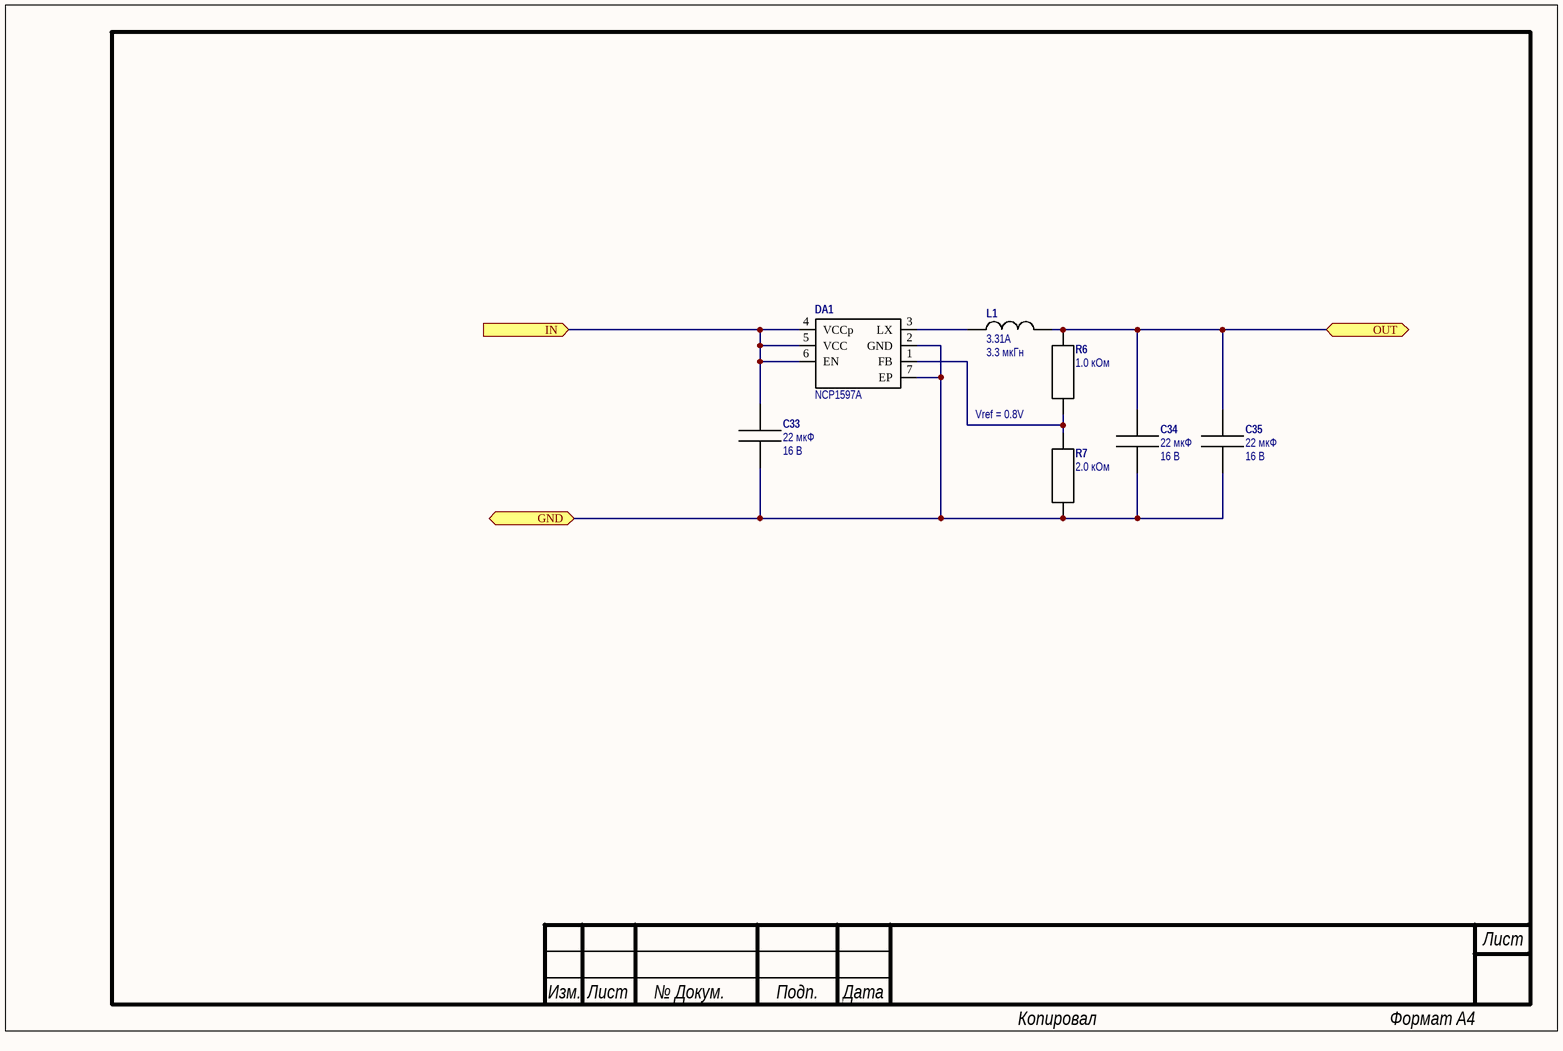
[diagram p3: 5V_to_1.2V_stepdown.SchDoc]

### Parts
C33  value 22 мкФ  VOLTAGE: 16 В  [C1210]  (hidden comment: 22 мкФ 20% 16 В 1210 X7R)
C34  value 22 мкФ  VOLTAGE: 16 В  [C1210]  (hidden comment: 22 мкФ 20% 16 В 1210 X7R)
C35  value 22 мкФ  VOLTAGE: 16 В  [C1210]  (hidden comment: 22 мкФ 20% 16 В 1210 X7R)
DA1  NCP1597A  [DFN6]
L1  value 3.3 мкГн  Curent: 3.31A  [DR73]  (hidden comment: DR73-3R3-R)
R6  value 1.0 кОм  [R0603]  (hidden comment: 1.0 кОм 0603 5%)
R7  value 2.0 кОм  [R0603]  (hidden comment: 2.0 кОм 0603 5%)

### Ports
GND, IN (in), OUT

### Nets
1.2V: C34.1 C35.1 L1.2 R6.2 ; port OUT
GND: C33.2 C34.2 C35.2 DA1.2(GND) DA1.7(EP) R7.1 ; port GND
VCC: C33.1 DA1.4(VCCp) DA1.5(VCC) DA1.6(EN) ; port IN
NetDA1_1: DA1.1(FB) R6.1 R7.2
NetDA1_3: DA1.3(LX) L1.1

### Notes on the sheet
- Vref = 0.8V
- Лист
- Изм.
- № Докум.
- Подп.
- Дата
- Копировал
- Формат
- А4

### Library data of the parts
C33-C35 = 22 мкФ 16 В: конденсатор керамический; articul: 727; Library Reference: capacitor
DA1 = NCP1597A: 1 MHz, 2.0 A Synchronous  Buck Regulator
L1 = DR73-3R3-R: катушка индуктивности; Library Reference: Inductor
R6 = 1.0 кОм 0603 5%: резистор постоянный; articul: 720
R7 = 2.0 кОм 0603 5%: резистор постоянный; articul: 915

## Sheet 5V_to_2.5V_stepdown.SchDoc
size A4
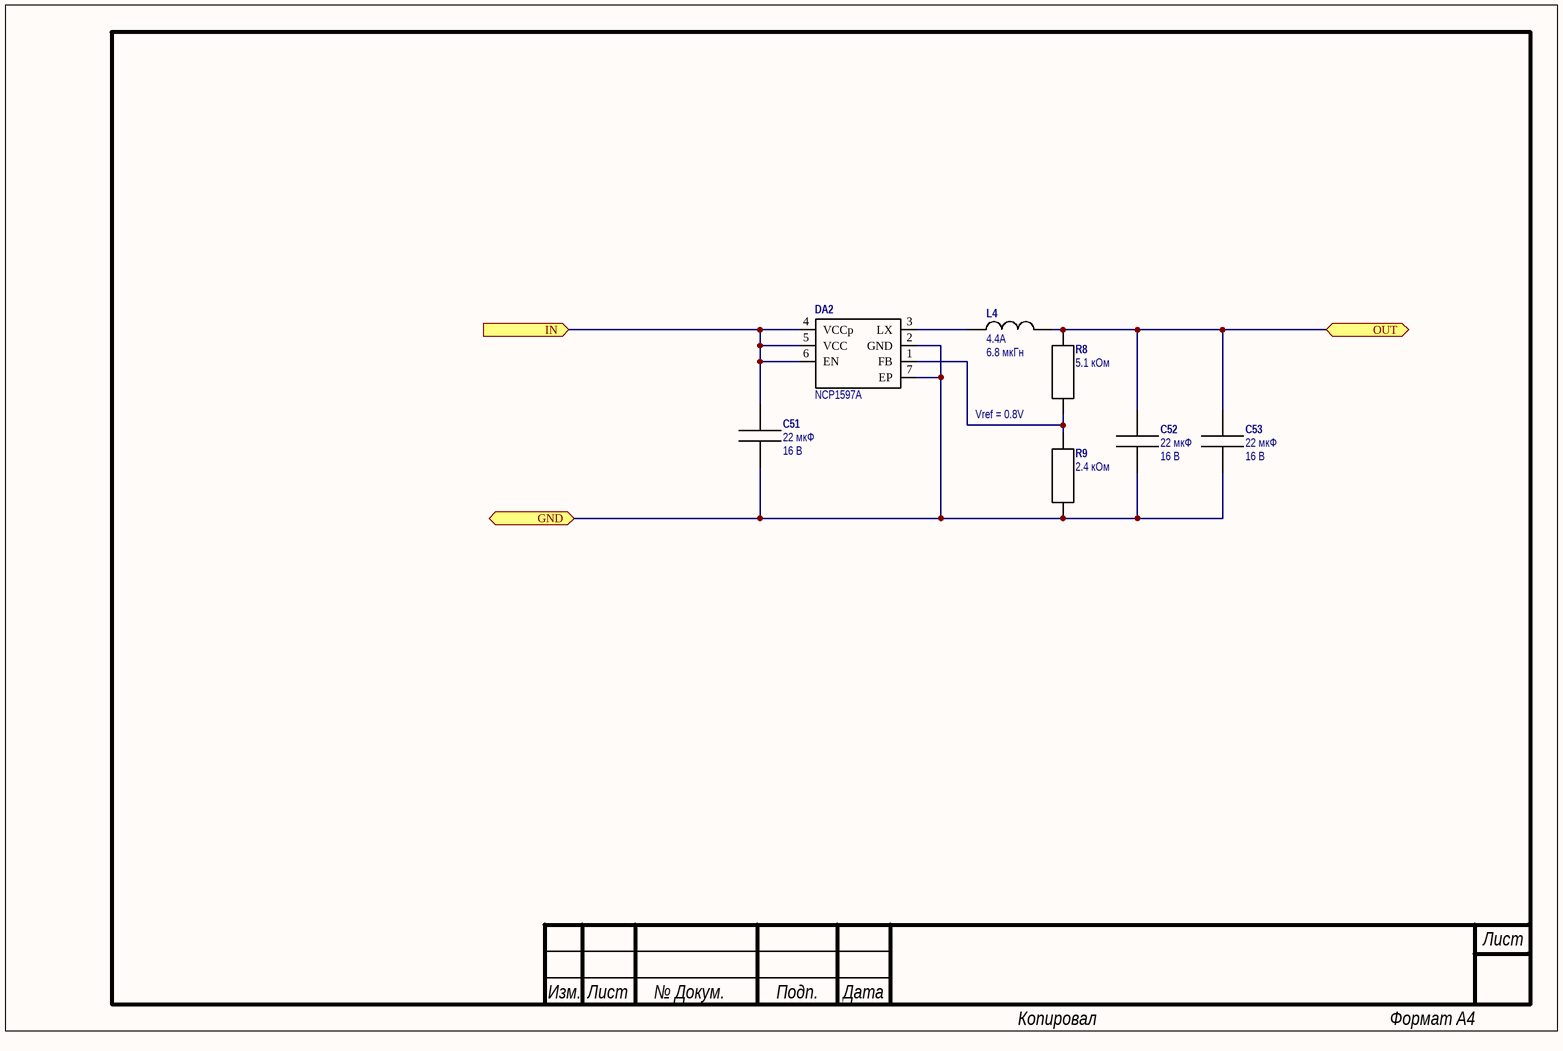
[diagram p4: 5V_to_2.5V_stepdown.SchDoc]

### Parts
C51  value 22 мкФ  VOLTAGE: 16 В  [C1210]  (hidden comment: 22 мкФ 20% 16 В 1210 X7R)
C52  value 22 мкФ  VOLTAGE: 16 В  [C1210]  (hidden comment: 22 мкФ 20% 16 В 1210 X7R)
C53  value 22 мкФ  VOLTAGE: 16 В  [C1210]  (hidden comment: 22 мкФ 20% 16 В 1210 X7R)
DA2  NCP1597A  [DFN6]
L4  value 6.8 мкГн  Curent: 4.4A  [CDRH8D43]  (hidden comment: CDRH8D43NP-6R8NC)
R8  value 5.1 кОм  [R0603]  (hidden comment: 5.1 кОм 0603 5%)
R9  value 2.4 кОм  [R0603]  (hidden comment: 2.4 кОм 0603 5%)

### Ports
GND, IN (in), OUT

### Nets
2.5V: C52.1 C53.1 L4.2 R8.2 ; port OUT
GND: C51.2 C52.2 C53.2 DA2.2(GND) DA2.7(EP) R9.1 ; port GND
VCC: C51.1 DA2.4(VCCp) DA2.5(VCC) DA2.6(EN) ; port IN
NetDA2_1: DA2.1(FB) R8.1 R9.2
NetDA2_3: DA2.3(LX) L4.1

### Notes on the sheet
- Vref = 0.8V
- Лист
- Изм.
- № Докум.
- Подп.
- Дата
- Копировал
- Формат
- А4

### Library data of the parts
C51-C53 = 22 мкФ 16 В: as C33 on sheet 5V_to_1.2V_stepdown
DA2 = NCP1597A: 1 MHz, 2.0 A Synchronous  Buck Regulator
L4 = CDRH8D43NP-6R8NC: катушка индуктивности; Library Reference: Inductor
R8 = 5.1 кОм 0603 5%: резистор постоянный; articul: 917
R9 = 2.4 кОм 0603 5%: резистор постоянный; articul: 0

## Sheet 5V_to_3.3V_stepdown.SchDoc
size A4
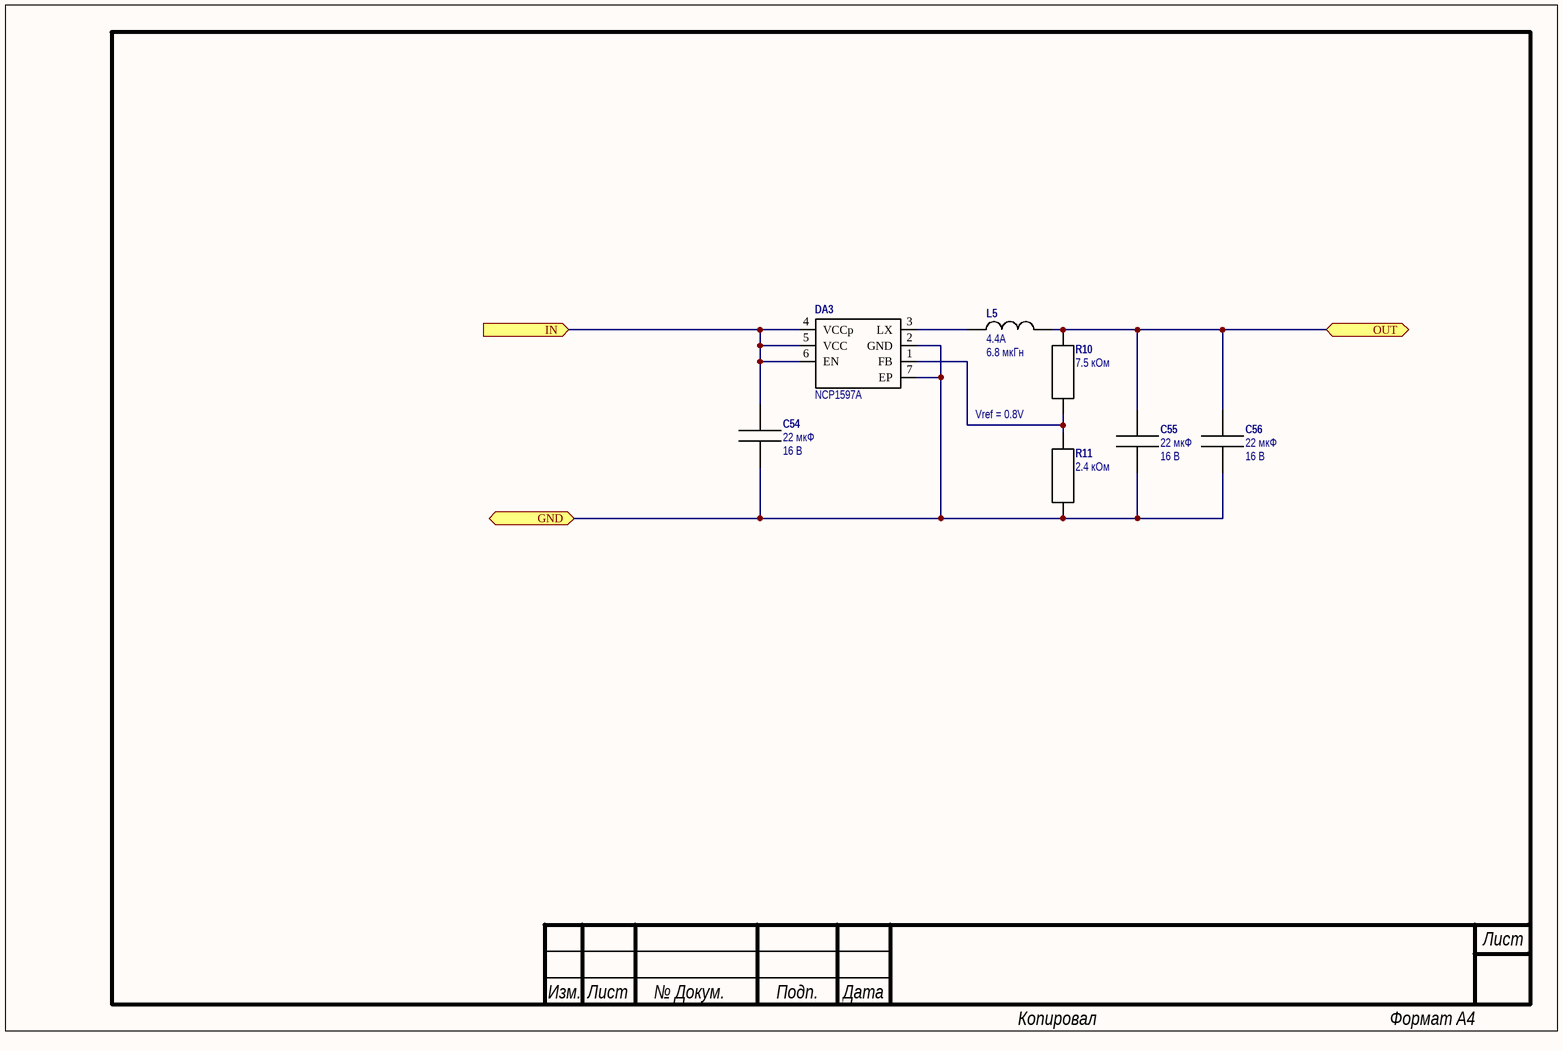
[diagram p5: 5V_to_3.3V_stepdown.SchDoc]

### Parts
C54  value 22 мкФ  VOLTAGE: 16 В  [C1210]  (hidden comment: 22 мкФ 20% 16 В 1210 X7R)
C55  value 22 мкФ  VOLTAGE: 16 В  [C1210]  (hidden comment: 22 мкФ 20% 16 В 1210 X7R)
C56  value 22 мкФ  VOLTAGE: 16 В  [C1210]  (hidden comment: 22 мкФ 20% 16 В 1210 X7R)
DA3  NCP1597A  [DFN6]
L5  value 6.8 мкГн  Curent: 4.4A  [CDRH8D43]  (hidden comment: CDRH8D43NP-6R8NC)
R10  value 7.5 кОм  [R0603]  (hidden comment: 7.5 кОм 0603 5%)
R11  value 2.4 кОм  [R0603]  (hidden comment: 2.4 кОм 0603 5%)

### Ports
GND, IN (in), OUT

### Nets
3.3V: C55.1 C56.1 L5.2 R10.2 ; port OUT
GND: C54.2 C55.2 C56.2 DA3.2(GND) DA3.7(EP) R11.1 ; port GND
VCC: C54.1 DA3.4(VCCp) DA3.5(VCC) DA3.6(EN) ; port IN
NetDA3_1: DA3.1(FB) R10.1 R11.2
NetDA3_3: DA3.3(LX) L5.1

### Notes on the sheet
- Vref = 0.8V
- Лист
- Изм.
- № Докум.
- Подп.
- Дата
- Копировал
- Формат
- А4

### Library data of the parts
C54-C56 = 22 мкФ 16 В: as C33 on sheet 5V_to_1.2V_stepdown
DA3 = NCP1597A: 1 MHz, 2.0 A Synchronous  Buck Regulator
L5 = CDRH8D43NP-6R8NC: as L4 on sheet 5V_to_2.5V_stepdown
R10 = 7.5 кОм 0603 5%: резистор постоянный; articul: 0
R11 = 2.4 кОм 0603 5%: резистор постоянный; articul: 0

## Sheet 5A Stepdown 5V.SchDoc
size A4
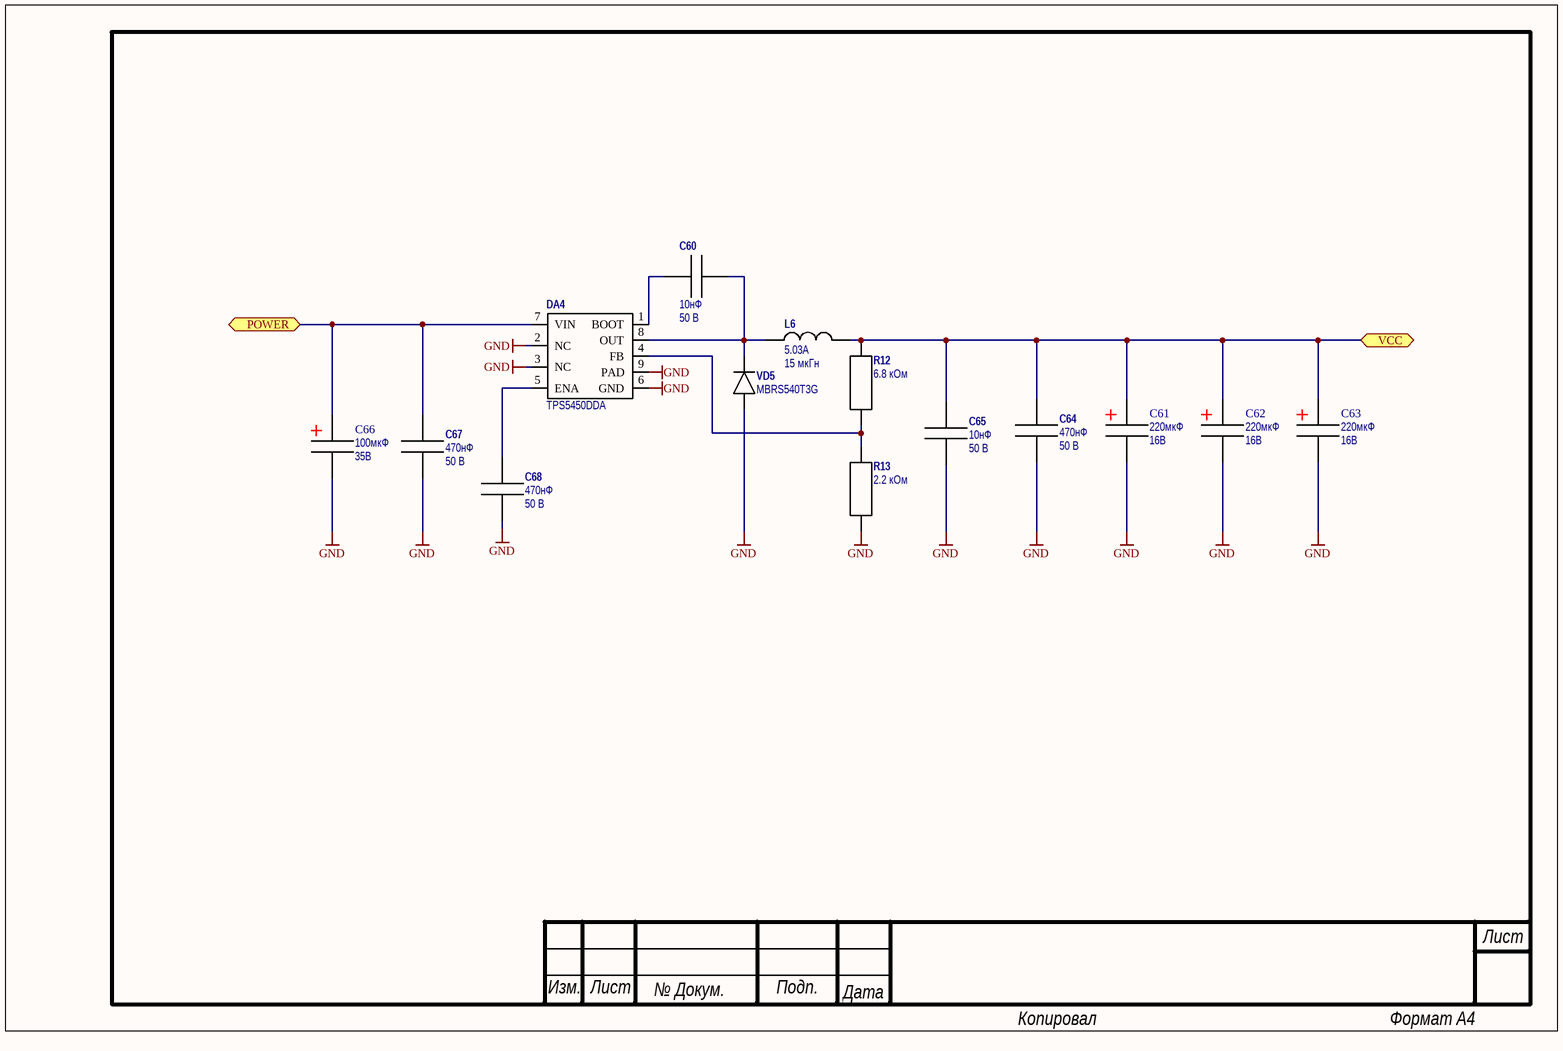
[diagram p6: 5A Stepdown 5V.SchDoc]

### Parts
C60  value 10нФ  VOLTAGE: 50 В  [C0805]  (hidden comment: 10нФ 10% 50 В)
C61  value 220мкФ  VOLTAGE: 16В  [ELCAP_SMD_6.3x8]  (hidden comment: 220мкФ 16В 6.3x8)
C62  value 220мкФ  VOLTAGE: 16В  [ELCAP_SMD_6.3x8]  (hidden comment: 220мкФ 16В 6.3x8)
C63  value 220мкФ  VOLTAGE: 16В  [ELCAP_SMD_6.3x8]  (hidden comment: 220мкФ 16В 6.3x8)
C64  value 470нФ  VOLTAGE: 50 В  [C0805]  (hidden comment: 470нФ 10% 50 В)
C65  value 10нФ  VOLTAGE: 50 В  [C0805]  (hidden comment: 10нФ 10% 50 В)
C66  value 100мкФ  VOLTAGE: 35В  [ELCAP_SMD_6.3x8]  (hidden comment: 100мкФ 35В 6.3x8)
C67  value 470нФ  VOLTAGE: 50 В  [C0805]  (hidden comment: 470нФ 10% 50 В)
C68  value 470нФ  VOLTAGE: 50 В  [C0805]  (hidden comment: 470нФ 10% 50 В)
DA4  TPS5450DDA  [HSOP8]
L6  value 15 мкГн  Curent: 5.03A  [DR127]  (hidden comment: DR127-150-R)
R12  value 6.8 кОм  [R0603]  (hidden comment: 6.8 кОм 0603 5%)
R13  value 2.2 кОм  [R0603]  (hidden comment: 2.2 кОм 0603 5%)
VD5  MBRS540T3G  [DO-214AB (SMC)]

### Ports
POWER, VCC

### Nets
GND: C61.2 C62.2 C63.2 C64.2 C65.2 C66.2 C67.2 C68.2 DA4.2(NC) DA4.3(NC) DA4.6(GND) DA4.9(PAD) R13.1 VD5.1
POWER: C66.1 C67.1 DA4.7(VIN) ; port POWER
VCC: C61.1 C62.1 C63.1 C64.1 C65.1 L6.2 R12.2 ; port VCC
NetC60_1: C60.1 DA4.1(BOOT)
NetC60_2: C60.2 DA4.8(OUT) L6.1 VD5.2
NetC68_1: C68.1 DA4.5(ENA)
NetDA4_4: DA4.4(FB) R12.1 R13.2

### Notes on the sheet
- Лист
- Изм.
- № Докум.
- Подп.
- Дата
- Копировал
- Формат
- А4

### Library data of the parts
C60 C65 = 10нФ 50 В: конденсатор керамический SMD; articul: 398; Library Reference: capacitor
C61-C63 = 220мкФ 16В 6.3x8: конденсатор электролитический SMD; articul: 11; Library Reference: CAP
C64 C67 C68 = 470нФ 50 В: конденсатор керамический SMD; articul: 389; Library Reference: capacitor
C66 = 100мкФ 35В 6.3x8: as C57 on sheet Power
DA4 = TPS5450DDA: STEP-DOWN 500kHz
L6 = DR127-150-R: катушка индуктивности; Library Reference: Inductor
R12 = 6.8 кОм 0603 5%: резистор постоянный; articul: 0
R13 = 2.2 кОм 0603 5%: резистор постоянный; articul: 719
VD5 = MBRS540T3G: as VD1 on sheet Power

## Sheet 5V_to_1.8V_stepdown.SchDoc
size A4
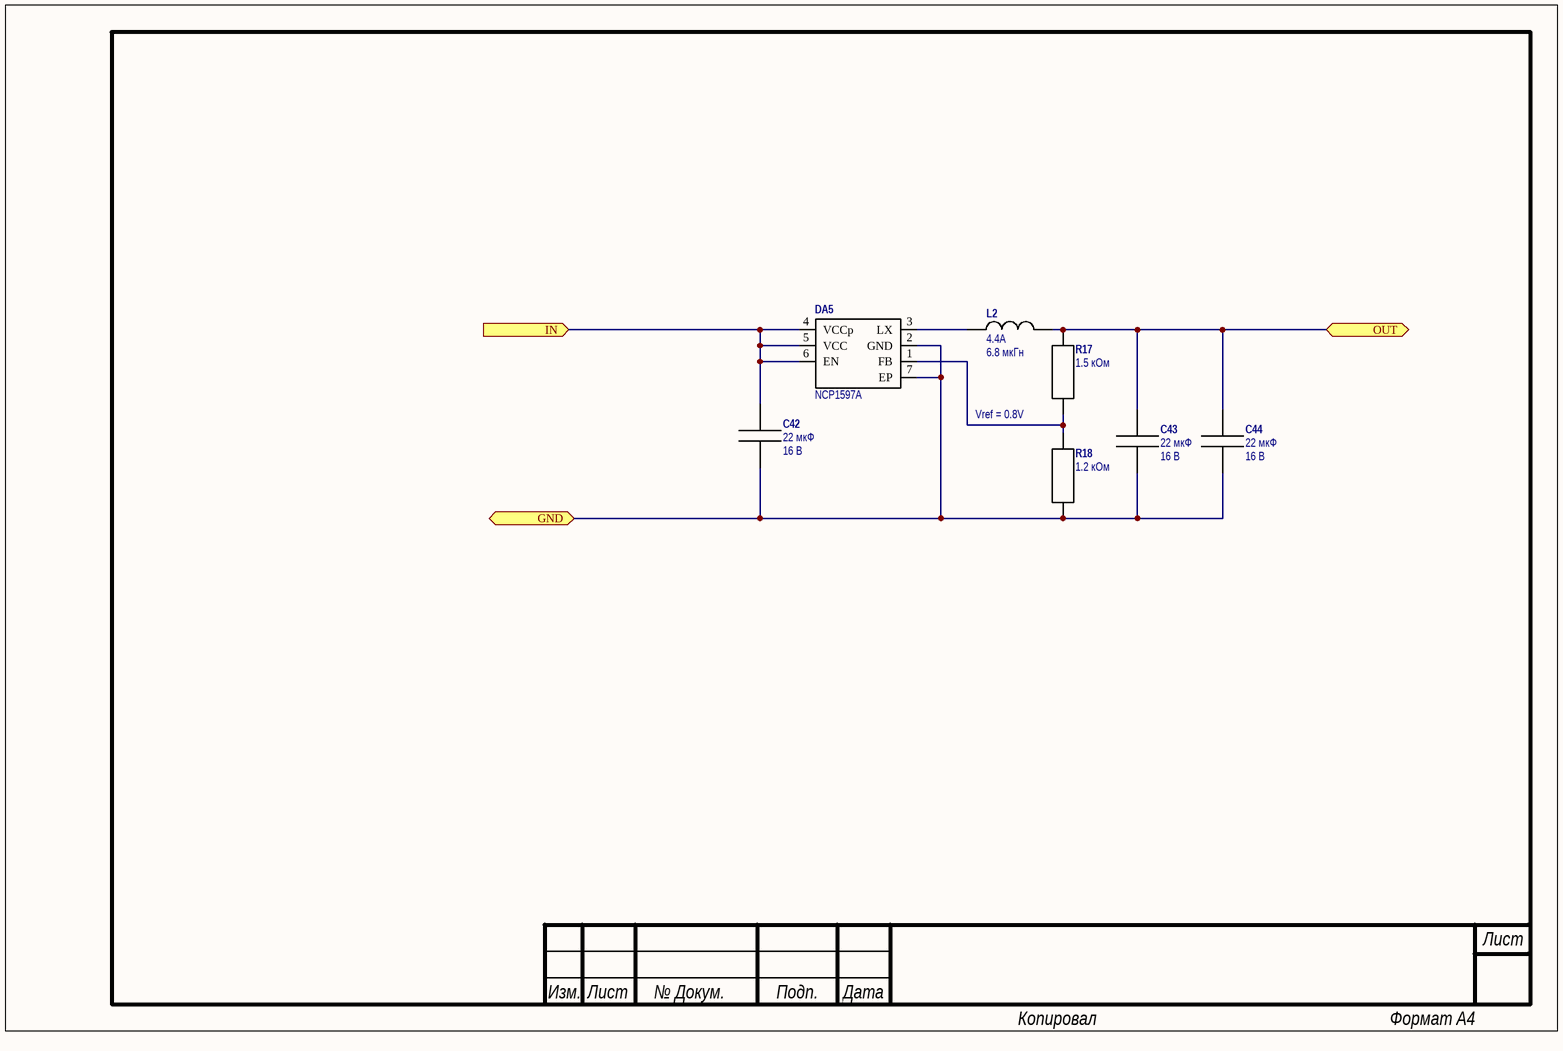
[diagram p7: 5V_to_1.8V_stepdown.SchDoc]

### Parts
C42  value 22 мкФ  VOLTAGE: 16 В  [C1210]  (hidden comment: 22 мкФ 20% 16 В 1210 X7R)
C43  value 22 мкФ  VOLTAGE: 16 В  [C1210]  (hidden comment: 22 мкФ 20% 16 В 1210 X7R)
C44  value 22 мкФ  VOLTAGE: 16 В  [C1210]  (hidden comment: 22 мкФ 20% 16 В 1210 X7R)
DA5  NCP1597A  [DFN6]
L2  value 6.8 мкГн  Curent: 4.4A  [CDRH8D43]  (hidden comment: CDRH8D43NP-6R8NC)
R17  value 1.5 кОм  [R0603]  (hidden comment: 1.5 кОм 0603 5%)
R18  value 1.2 кОм  [R0603]  (hidden comment: 1.2 кОм 0603 5%)

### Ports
GND, IN (in), OUT

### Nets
1.8V: C43.1 C44.1 L2.2 R17.2 ; port OUT
GND: C42.2 C43.2 C44.2 DA5.2(GND) DA5.7(EP) R18.1 ; port GND
VCC: C42.1 DA5.4(VCCp) DA5.5(VCC) DA5.6(EN) ; port IN
NetDA5_1: DA5.1(FB) R17.1 R18.2
NetDA5_3: DA5.3(LX) L2.1

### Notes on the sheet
- Vref = 0.8V
- Лист
- Изм.
- № Докум.
- Подп.
- Дата
- Копировал
- Формат
- А4

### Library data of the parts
C42-C44 = 22 мкФ 16 В: as C33 on sheet 5V_to_1.2V_stepdown
DA5 = NCP1597A: 1 MHz, 2.0 A Synchronous  Buck Regulator
L2 = CDRH8D43NP-6R8NC: as L4 on sheet 5V_to_2.5V_stepdown
R17 = 1.5 кОм 0603 5%: резистор постоянный; articul: 0
R18 = 1.2 кОм 0603 5%: резистор постоянный; articul: 0

## Sheet FPGA2.SchDoc
size custom portrait
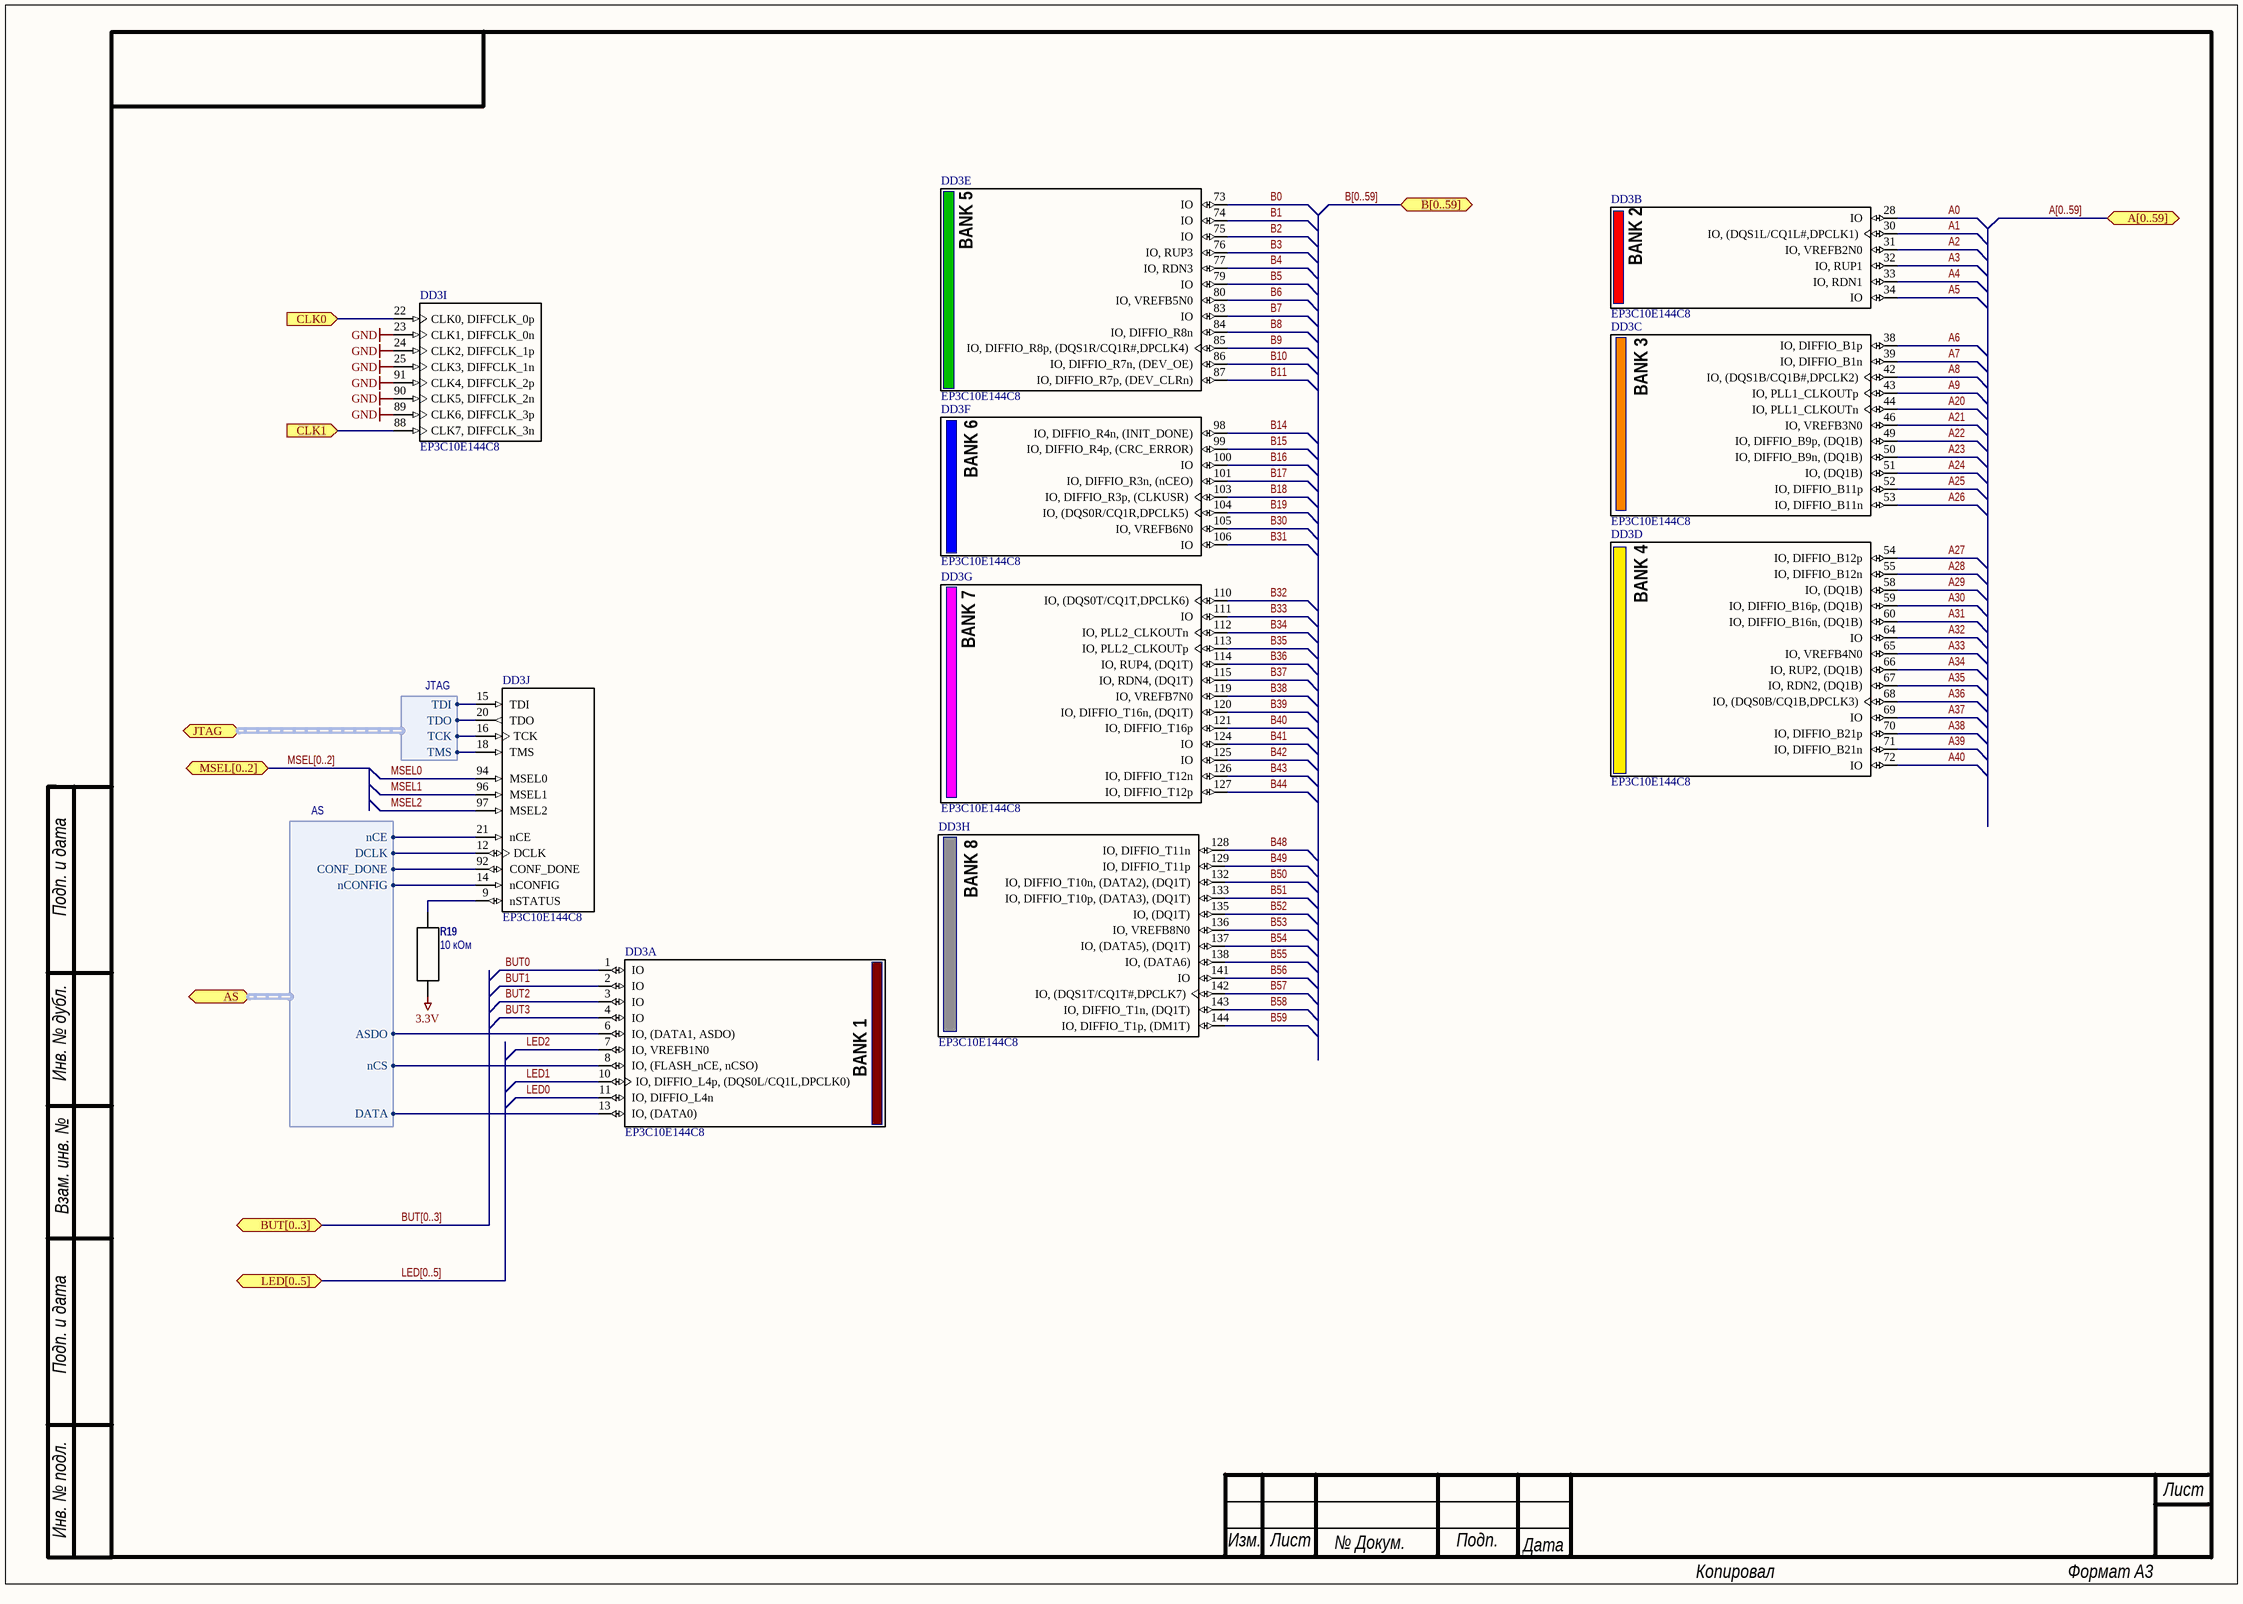
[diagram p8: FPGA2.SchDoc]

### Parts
DD3  EP3C10E144C8  [EQFP-144]  (parts A,B,C,D,E,F,G,H,I,J of 13)
R19  value 10 кОм  [R0603]  (hidden comment: 10 кОм 0603 5%)

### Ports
A[0..59], AS (harness AS), B[0..59], BUT[0..3], CLK0 (in), CLK1 (in), JTAG (harness JTAG), LED[0..5], MSEL[0..2]

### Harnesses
JTAG: TCK, TDO, TMS, TDI
AS: nCE, DCLK, CONF_DONE, nCONFIG, ASDO, nCS, DATA

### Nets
3.3V: R19.2
GND: DD3.23(CLK1,_DIFFCLK_0n) DD3.24(CLK2,_DIFFCLK_1p) DD3.25(CLK3,_DIFFCLK_1n) DD3.89(CLK6,_DIFFCLK_3p) DD3.90(CLK5,_DIFFCLK_2n) DD3.91(CLK4,_DIFFCLK_2p)
A0: DD3.28(IO)
A1: DD3.30(IO,_(DQS1L/CQ1L#,DPCLK1))
A2: DD3.31(IO,_VREFB2N0)
A3: DD3.32(IO,_RUP1)
A4: DD3.33(IO,_RDN1)
A5: DD3.34(IO)
A6: DD3.38(IO,_DIFFIO_B1p)
A7: DD3.39(IO,_DIFFIO_B1n)
A8: DD3.42(IO,_(DQS1B/CQ1B#,DPCLK2))
A9: DD3.43(IO,_PLL1_CLKOUTp)
A20: DD3.44(IO,_PLL1_CLKOUTn)
A21: DD3.46(IO,_VREFB3N0)
A22: DD3.49(IO,_DIFFIO_B9p,_(DQ1B))
A23: DD3.50(IO,_DIFFIO_B9n,_(DQ1B))
A24: DD3.51(IO,_(DQ1B))
A25: DD3.52(IO,_DIFFIO_B11p)
A26: DD3.53(IO,_DIFFIO_B11n)
A27: DD3.54(IO,_DIFFIO_B12p)
A28: DD3.55(IO,_DIFFIO_B12n)
A29: DD3.58(IO,_(DQ1B))
A30: DD3.59(IO,_DIFFIO_B16p,_(DQ1B))
A31: DD3.60(IO,_DIFFIO_B16n,_(DQ1B))
A32: DD3.64(IO)
A33: DD3.65(IO,_VREFB4N0)
A34: DD3.66(IO,_RUP2,_(DQ1B))
A35: DD3.67(IO,_RDN2,_(DQ1B))
A36: DD3.68(IO,_(DQS0B/CQ1B,DPCLK3))
A37: DD3.69(IO)
A38: DD3.70(IO,_DIFFIO_B21p)
A39: DD3.71(IO,_DIFFIO_B21n)
A40: DD3.72(IO)
ASD: DD3.6(IO,_(DATA1,_ASDO)) ; port AS.ASDO
B0: DD3.73(IO)
B1: DD3.74(IO)
B2: DD3.75(IO)
B3: DD3.76(IO,_RUP3)
B4: DD3.77(IO,_RDN3)
B5: DD3.79(IO)
B6: DD3.80(IO,_VREFB5N0)
B7: DD3.83(IO)
B8: DD3.84(IO,_DIFFIO_R8n)
B9: DD3.85(IO,_DIFFIO_R8p,_(DQS1R/CQ1R#,DPCLK4))
B10: DD3.86(IO,_DIFFIO_R7n,_(DEV_OE))
B11: DD3.87(IO,_DIFFIO_R7p,_(DEV_CLRn))
B14: DD3.98(IO,_DIFFIO_R4n,_(INIT_DONE))
B15: DD3.99(IO,_DIFFIO_R4p,_(CRC_ERROR))
B16: DD3.100(IO)
B17: DD3.101(IO,_DIFFIO_R3n,_(nCEO))
B18: DD3.103(IO,_DIFFIO_R3p,_(CLKUSR))
B19: DD3.104(IO,_(DQS0R/CQ1R,DPCLK5))
B30: DD3.105(IO,_VREFB6N0)
B31: DD3.106(IO)
B32: DD3.110(IO,_(DQS0T/CQ1T,DPCLK6))
B33: DD3.111(IO)
B34: DD3.112(IO,_PLL2_CLKOUTn)
B35: DD3.113(IO,_PLL2_CLKOUTp)
B36: DD3.114(IO,_RUP4,_(DQ1T))
B37: DD3.115(IO,_RDN4,_(DQ1T))
B38: DD3.119(IO,_VREFB7N0)
B39: DD3.120(IO,_DIFFIO_T16n,_(DQ1T))
B40: DD3.121(IO,_DIFFIO_T16p)
B41: DD3.124(IO)
B42: DD3.125(IO)
B43: DD3.126(IO,_DIFFIO_T12n)
B44: DD3.127(IO,_DIFFIO_T12p)
B48: DD3.128(IO,_DIFFIO_T11n)
B49: DD3.129(IO,_DIFFIO_T11p)
B50: DD3.132(IO,_DIFFIO_T10n,_(DATA2),_(DQ1T))
B51: DD3.133(IO,_DIFFIO_T10p,_(DATA3),_(DQ1T))
B52: DD3.135(IO,_(DQ1T))
B53: DD3.136(IO,_VREFB8N0)
B54: DD3.137(IO,_(DATA5),_(DQ1T))
B55: DD3.138(IO,_(DATA6))
B56: DD3.141(IO)
B57: DD3.142(IO,_(DQS1T/CQ1T#,DPCLK7))
B58: DD3.143(IO,_DIFFIO_T1n,_(DQ1T))
B59: DD3.144(IO,_DIFFIO_T1p,_(DM1T))
BUT0: DD3.1(IO)
BUT1: DD3.2(IO)
BUT2: DD3.3(IO)
BUT3: DD3.4(IO)
CLK0: DD3.22(CLK0,_DIFFCLK_0p) ; port CLK0
CLK1: DD3.88(CLK7,_DIFFCLK_3n) ; port CLK1
CONFIG_DONE: DD3.92(CONF_DONE) ; port AS.CONF_DONE
DATA: DD3.13(IO,_(DATA0)) ; port AS.DATA
DCLK: DD3.12(DCLK) ; port AS.DCLK
JTAG.TCK: DD3.16(TCK) ; port JTAG.TCK
JTAG.TDI: DD3.15(TDI) ; port JTAG.TDI
JTAG.TDO: DD3.20(TDO) ; port JTAG.TDO
JTAG.TMS: DD3.18(TMS) ; port JTAG.TMS
LED0: DD3.11(IO,_DIFFIO_L4n)
LED1: DD3.10(IO,_DIFFIO_L4p,_(DQS0L/CQ1L,DPCLK0))
LED2: DD3.7(IO,_VREFB1N0)
MSEL0: DD3.94(MSEL0)
MSEL1: DD3.96(MSEL1)
MSEL2: DD3.97(MSEL2)
nCE: DD3.21(nCE) ; port AS.nCE
nCONFIG: DD3.14(nCONFIG) ; port AS.nCONFIG
nCS: DD3.8(IO,_(FLASH_nCE,_nCSO)) ; port AS.nCS
NetDD3_9: DD3.9(nSTATUS) R19.1

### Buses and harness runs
bus A[0..59] = port A[0..59]
bus B[0..59] = port B[0..59]
bus BUT[0..3] = port BUT[0..3]
bus LED[0..5] = port LED[0..5]
bus MSEL[0..2] = port MSEL[0..2]

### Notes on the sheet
- Подп. и дата
- Инв. № дубл.
- Взам. инв. №
- Инв. № подл.
- Лист
- Изм.
- № Докум.
- Подп.
- Дата
- Копировал
- Формат
- А3

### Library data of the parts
DD3 = EP3C10E144C8: as DD3 on sheet Power
R19 = 10 кОм 0603 5%: резистор постоянный; articul: 918

## Sheet A_PLD-80_IO.SchDoc
size custom portrait
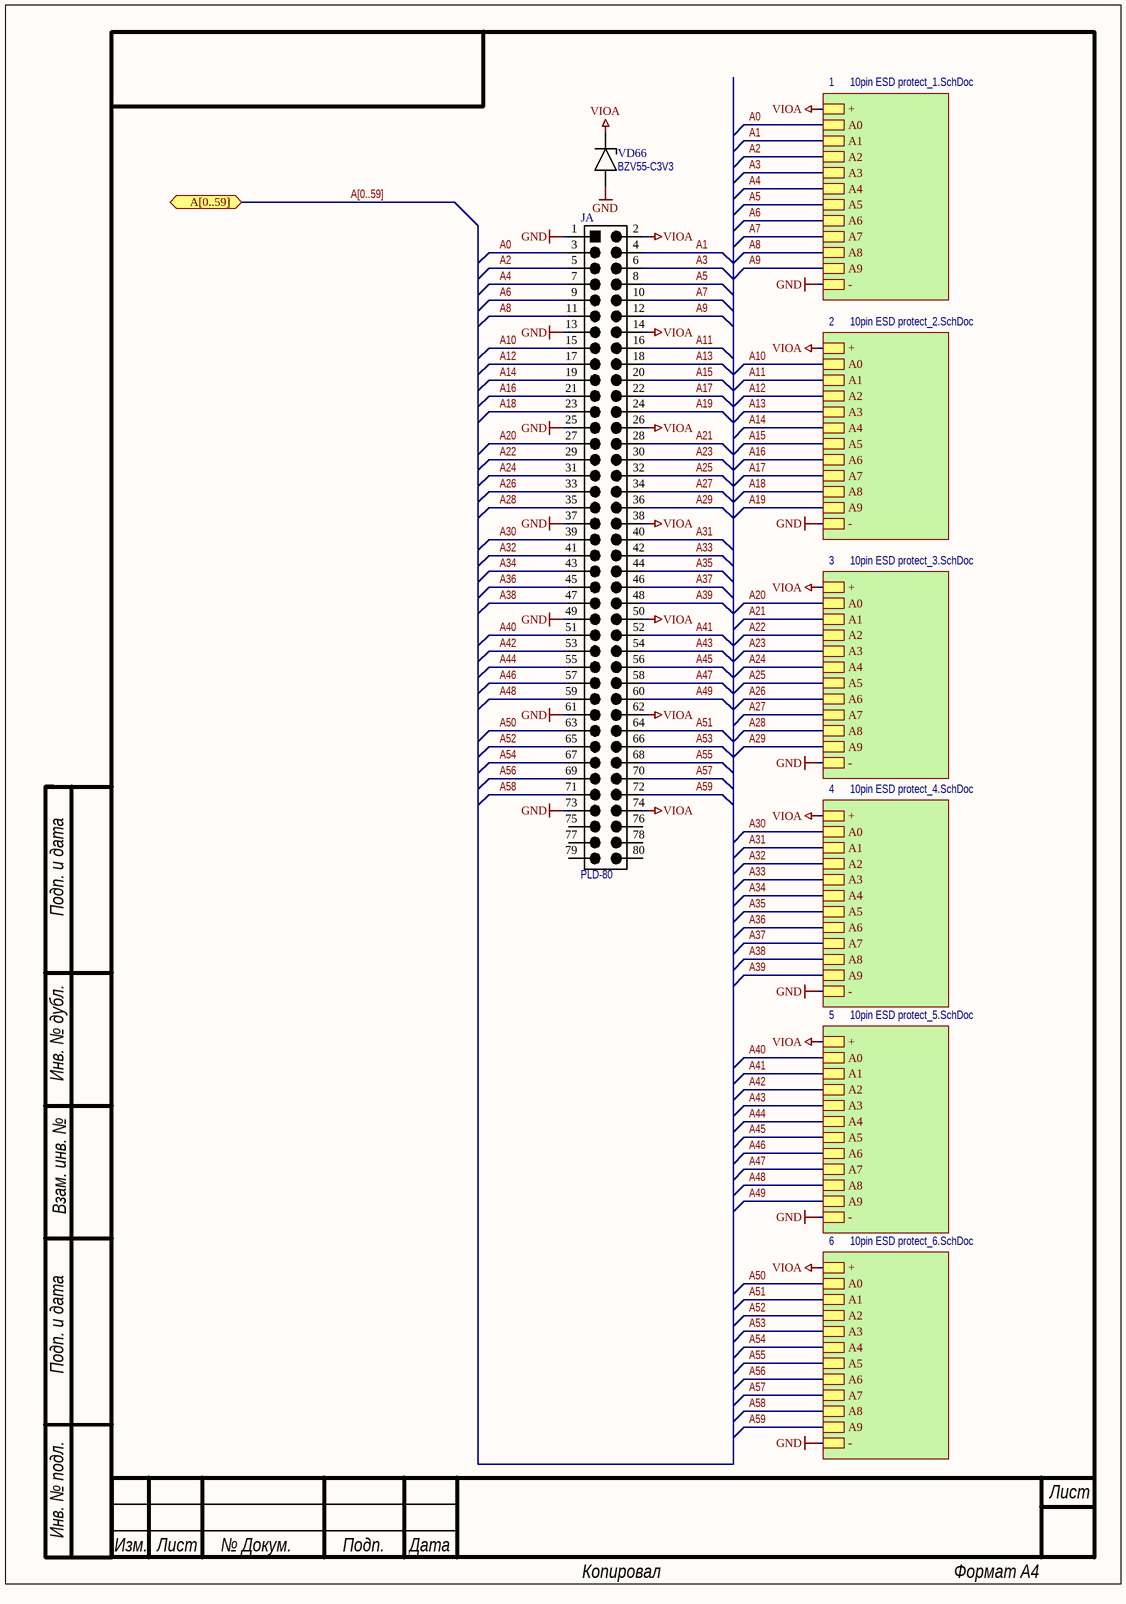
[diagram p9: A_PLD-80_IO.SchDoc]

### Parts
JA  PLD-80  [HEADER 2X40]
VD66  BZV55-C3V3  [SOD-80]

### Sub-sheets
1 = 10pin ESD protect_1.SchDoc: A0, A1, A2, A3, A4, A5, A6, A7, A8, A9, -, +
2 = 10pin ESD protect_2.SchDoc: A0, A1, A2, A3, A4, A5, A6, A7, A8, A9, -, +
3 = 10pin ESD protect_3.SchDoc: A0, A1, A2, A3, A4, A5, A6, A7, A8, A9, -, +
4 = 10pin ESD protect_4.SchDoc: A0, A1, A2, A3, A4, A5, A6, A7, A8, A9, -, +
5 = 10pin ESD protect_5.SchDoc: A0, A1, A2, A3, A4, A5, A6, A7, A8, A9, -, +
6 = 10pin ESD protect_6.SchDoc: A0, A1, A2, A3, A4, A5, A6, A7, A8, A9, -, +

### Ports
A[0..59]

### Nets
GND: JA.1 JA.13 JA.25 JA.37 JA.49 JA.61 JA.73 VD66.1 ; sheet 1/-, sheet 2/-, sheet 3/-, sheet 4/-, sheet 6/-, sheet 5/-
VIOA: JA.2 JA.14 JA.26 JA.38 JA.50 JA.62 JA.74 VD66.2 ; sheet 1/+, sheet 2/+, sheet 3/+, sheet 4/+, sheet 6/+, sheet 5/+
A0: JA.3 ; sheet 1/A0
A1: JA.4 ; sheet 1/A1
A2: JA.5 ; sheet 1/A2
A3: JA.6 ; sheet 1/A3
A4: JA.7 ; sheet 1/A4
A5: JA.8 ; sheet 1/A5
A6: JA.9 ; sheet 1/A6
A7: JA.10 ; sheet 1/A7
A8: JA.11 ; sheet 1/A8
A9: JA.12 ; sheet 1/A9
A10: JA.15 ; sheet 2/A0
A11: JA.16 ; sheet 2/A1
A12: JA.17 ; sheet 2/A2
A13: JA.18 ; sheet 2/A3
A14: JA.19 ; sheet 2/A4
A15: JA.20 ; sheet 2/A5
A16: JA.21 ; sheet 2/A6
A17: JA.22 ; sheet 2/A7
A18: JA.23 ; sheet 2/A8
A19: JA.24 ; sheet 2/A9
A20: JA.27 ; sheet 3/A0
A21: JA.28 ; sheet 3/A1
A22: JA.29 ; sheet 3/A2
A23: JA.30 ; sheet 3/A3
A24: JA.31 ; sheet 3/A4
A25: JA.32 ; sheet 3/A5
A26: JA.33 ; sheet 3/A6
A27: JA.34 ; sheet 3/A7
A28: JA.35 ; sheet 3/A8
A29: JA.36 ; sheet 3/A9
A30: JA.39 ; sheet 4/A0
A31: JA.40 ; sheet 4/A1
A32: JA.41 ; sheet 4/A2
A33: JA.42 ; sheet 4/A3
A34: JA.43 ; sheet 4/A4
A35: JA.44 ; sheet 4/A5
A36: JA.45 ; sheet 4/A6
A37: JA.46 ; sheet 4/A7
A38: JA.47 ; sheet 4/A8
A39: JA.48 ; sheet 4/A9
A40: JA.51 ; sheet 5/A0
A41: JA.52 ; sheet 5/A1
A42: JA.53 ; sheet 5/A2
A43: JA.54 ; sheet 5/A3
A44: JA.55 ; sheet 5/A4
A45: JA.56 ; sheet 5/A5
A46: JA.57 ; sheet 5/A6
A47: JA.58 ; sheet 5/A7
A48: JA.59 ; sheet 5/A8
A49: JA.60 ; sheet 5/A9
A50: JA.63 ; sheet 6/A0
A51: JA.64 ; sheet 6/A1
A52: JA.65 ; sheet 6/A2
A53: JA.66 ; sheet 6/A3
A54: JA.67 ; sheet 6/A4
A55: JA.68 ; sheet 6/A5
A56: JA.69 ; sheet 6/A6
A57: JA.70 ; sheet 6/A7
A58: JA.71 ; sheet 6/A8
A59: JA.72 ; sheet 6/A9

Not connected (* = marked no-connect by the designer): JA 75 76 77 78 79 80

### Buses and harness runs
bus A[0..59] = port A[0..59]

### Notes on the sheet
- Подп. и дата
- Инв. № дубл.
- Взам. инв. №
- Инв. № подл.
- Лист
- Изм.
- № Докум.
- Подп.
- Дата
- Копировал
- Формат
- А4

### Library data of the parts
JA = PLD-80: Штырьки на плату шаг 2,54 мм
VD66 = BZV55-C3V3: Стабилитрон 0,5Вт; articul: 343; Library Reference: ZENER

## Sheet 10pin ESD protect_1.SchDoc
size A4
Used 2 times, as channels A/1, B/1. Parts and nets are listed once, with the designators drawn on the sheet.
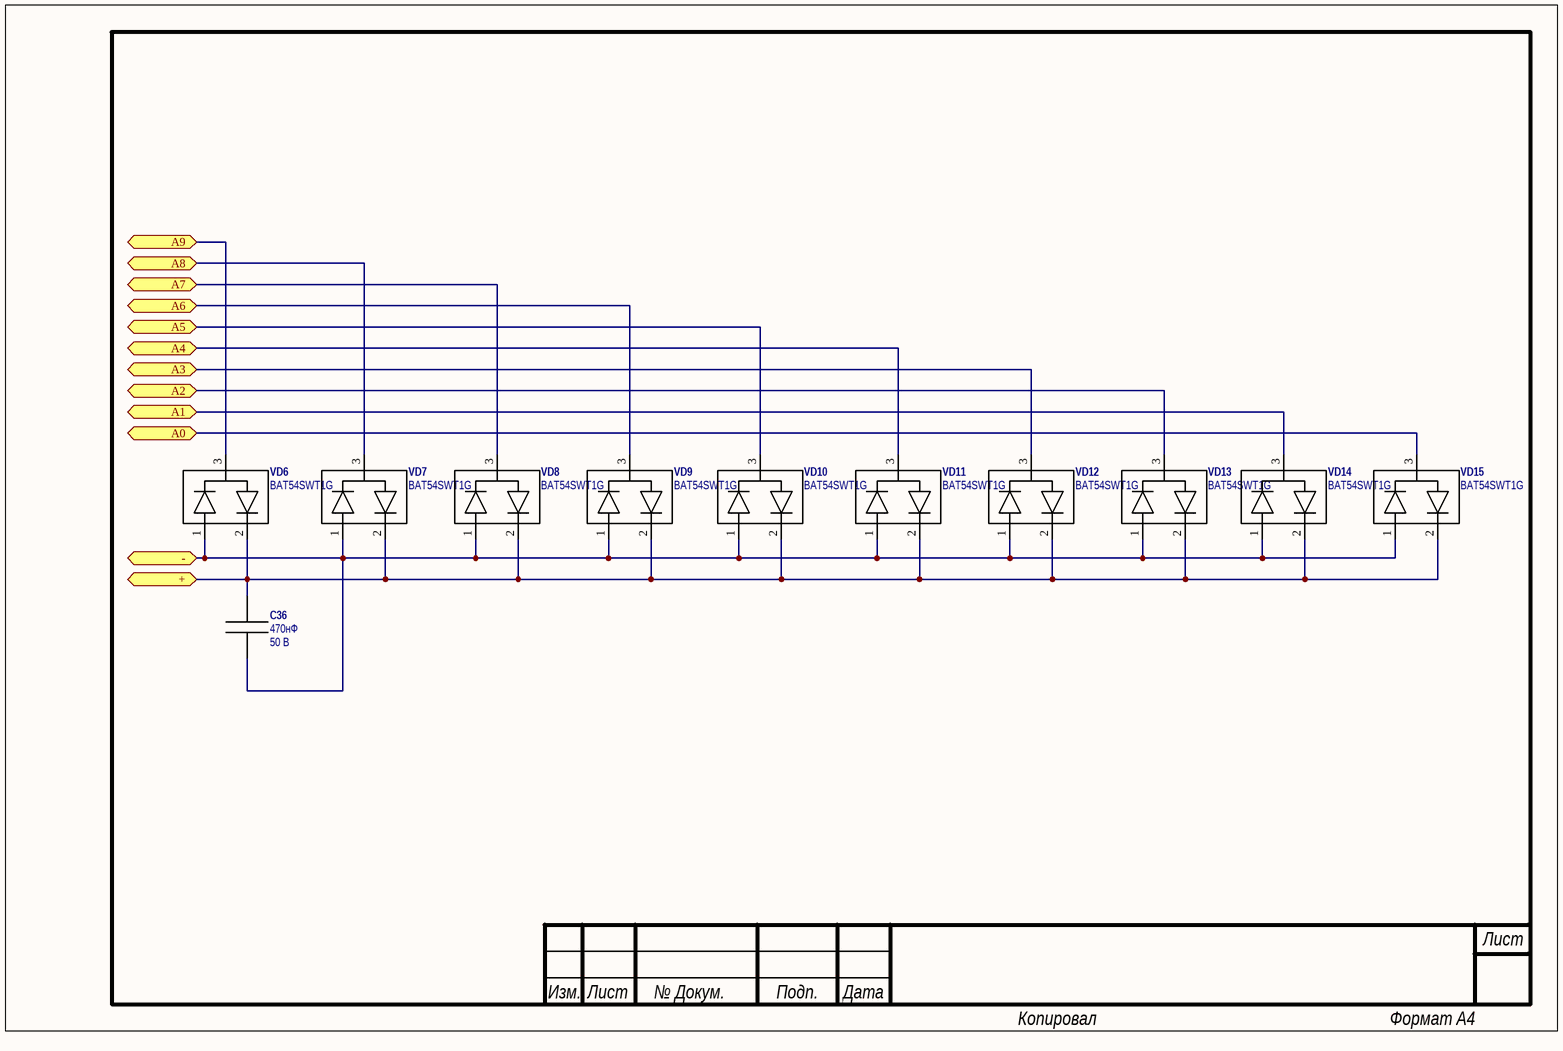
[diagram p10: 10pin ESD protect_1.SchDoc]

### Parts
C36  value 470нФ  VOLTAGE: 50 В  [C0805]  (hidden comment: 470нФ 10% 50 В)
VD6  BAT54SWT1G  [SC-70]
VD7  BAT54SWT1G  [SC-70]
VD8  BAT54SWT1G  [SC-70]
VD9  BAT54SWT1G  [SC-70]
VD10  BAT54SWT1G  [SC-70]
VD11  BAT54SWT1G  [SC-70]
VD12  BAT54SWT1G  [SC-70]
VD13  BAT54SWT1G  [SC-70]
VD14  BAT54SWT1G  [SC-70]
VD15  BAT54SWT1G  [SC-70]

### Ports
+, -, A0, A1, A2, A3, A4, A5, A6, A7, A8, A9

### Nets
+: C36.1 VD6.2 VD7.2 VD8.2 VD9.2 VD10.2 VD11.2 VD12.2 VD13.2 VD14.2 VD15.2 ; port +
-: C36.2 VD6.1 VD7.1 VD8.1 VD9.1 VD10.1 VD11.1 VD12.1 VD13.1 VD14.1 VD15.1 ; port -
A0: VD15.3 ; port A0
A1: VD14.3 ; port A1
A2: VD13.3 ; port A2
A3: VD12.3 ; port A3
A4: VD11.3 ; port A4
A5: VD10.3 ; port A5
A6: VD9.3 ; port A6
A7: VD8.3 ; port A7
A8: VD7.3 ; port A8
A9: VD6.3 ; port A9

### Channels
A/1: designators end in A; ports +=VIOA -=GND A0=A0 A1=A1 A2=A2 A3=A3 A4=A4 A5=A5 A6=A6 A7=A7 A8=A8 A9=A9
B/1: designators end in B; ports +=VIOB -=GND A0=B0 A1=B1 A2=B2 A3=B3 A4=B4 A5=B5 A6=B6 A7=B7 A8=B8 A9=B9

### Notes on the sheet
- Лист
- Изм.
- № Докум.
- Подп.
- Дата
- Копировал
- Формат
- А4

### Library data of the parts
C36 = 470нФ 50 В: as C64 on sheet 5A Stepdown 5V
VD6-VD15 = BAT54SWT1G: два диода Шоттки; articul: 1103

## Sheet 10pin ESD protect_2.SchDoc
size A4
Used 2 times, as channels A/2, B/2. Parts and nets are listed once, with the designators drawn on the sheet.
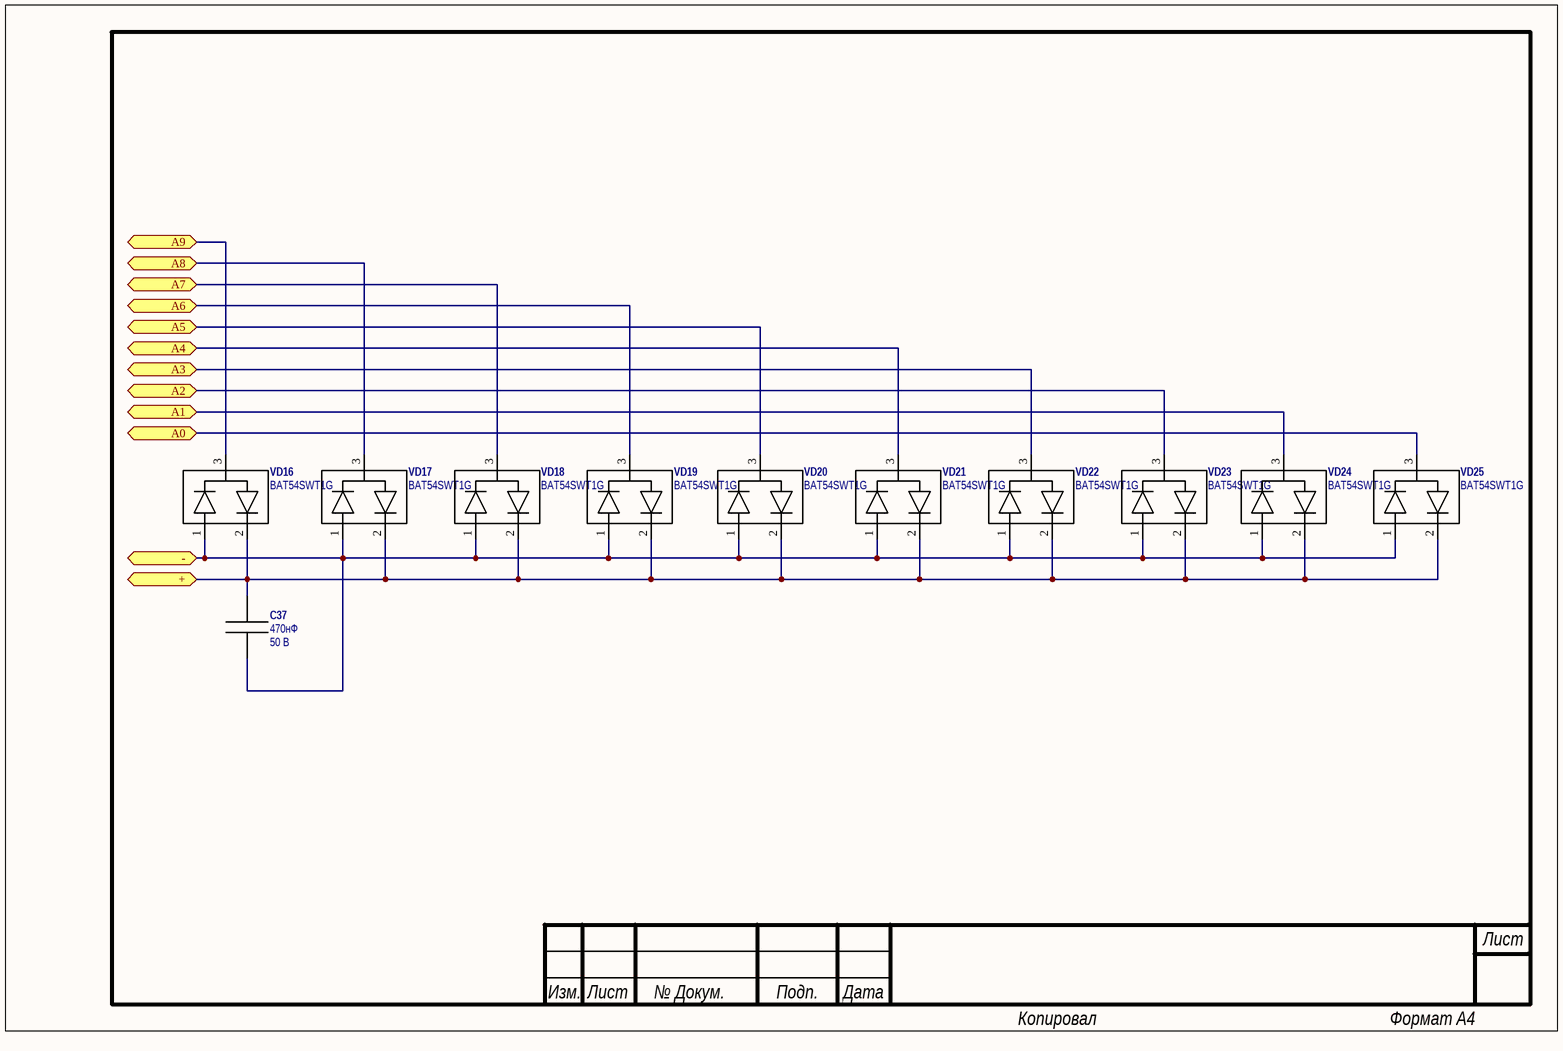
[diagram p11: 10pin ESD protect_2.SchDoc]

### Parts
C37  value 470нФ  VOLTAGE: 50 В  [C0805]  (hidden comment: 470нФ 10% 50 В)
VD16  BAT54SWT1G  [SC-70]
VD17  BAT54SWT1G  [SC-70]
VD18  BAT54SWT1G  [SC-70]
VD19  BAT54SWT1G  [SC-70]
VD20  BAT54SWT1G  [SC-70]
VD21  BAT54SWT1G  [SC-70]
VD22  BAT54SWT1G  [SC-70]
VD23  BAT54SWT1G  [SC-70]
VD24  BAT54SWT1G  [SC-70]
VD25  BAT54SWT1G  [SC-70]

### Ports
+, -, A0, A1, A2, A3, A4, A5, A6, A7, A8, A9

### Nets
+: C37.1 VD16.2 VD17.2 VD18.2 VD19.2 VD20.2 VD21.2 VD22.2 VD23.2 VD24.2 VD25.2 ; port +
-: C37.2 VD16.1 VD17.1 VD18.1 VD19.1 VD20.1 VD21.1 VD22.1 VD23.1 VD24.1 VD25.1 ; port -
A0: VD25.3 ; port A0
A1: VD24.3 ; port A1
A2: VD23.3 ; port A2
A3: VD22.3 ; port A3
A4: VD21.3 ; port A4
A5: VD20.3 ; port A5
A6: VD19.3 ; port A6
A7: VD18.3 ; port A7
A8: VD17.3 ; port A8
A9: VD16.3 ; port A9

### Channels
A/2: designators end in A; ports +=VIOA -=GND A0=A10 A1=A11 A2=A12 A3=A13 A4=A14 A5=A15 A6=A16 A7=A17 A8=A18 A9=A19
B/2: designators end in B; ports +=VIOB -=GND A0=B10 A1=B11 A2=B12 A3=B13 A4=B14 A5=B15 A6=B16 A7=B17 A8=B18 A9=B19

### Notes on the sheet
- Лист
- Изм.
- № Докум.
- Подп.
- Дата
- Копировал
- Формат
- А4

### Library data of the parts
C37 = 470нФ 50 В: as C64 on sheet 5A Stepdown 5V
VD16-VD25 = BAT54SWT1G: два диода Шоттки; articul: 1103

## Sheet 10pin ESD protect_3.SchDoc
size A4
Used 2 times, as channels A/3, B/3. Parts and nets are listed once, with the designators drawn on the sheet.
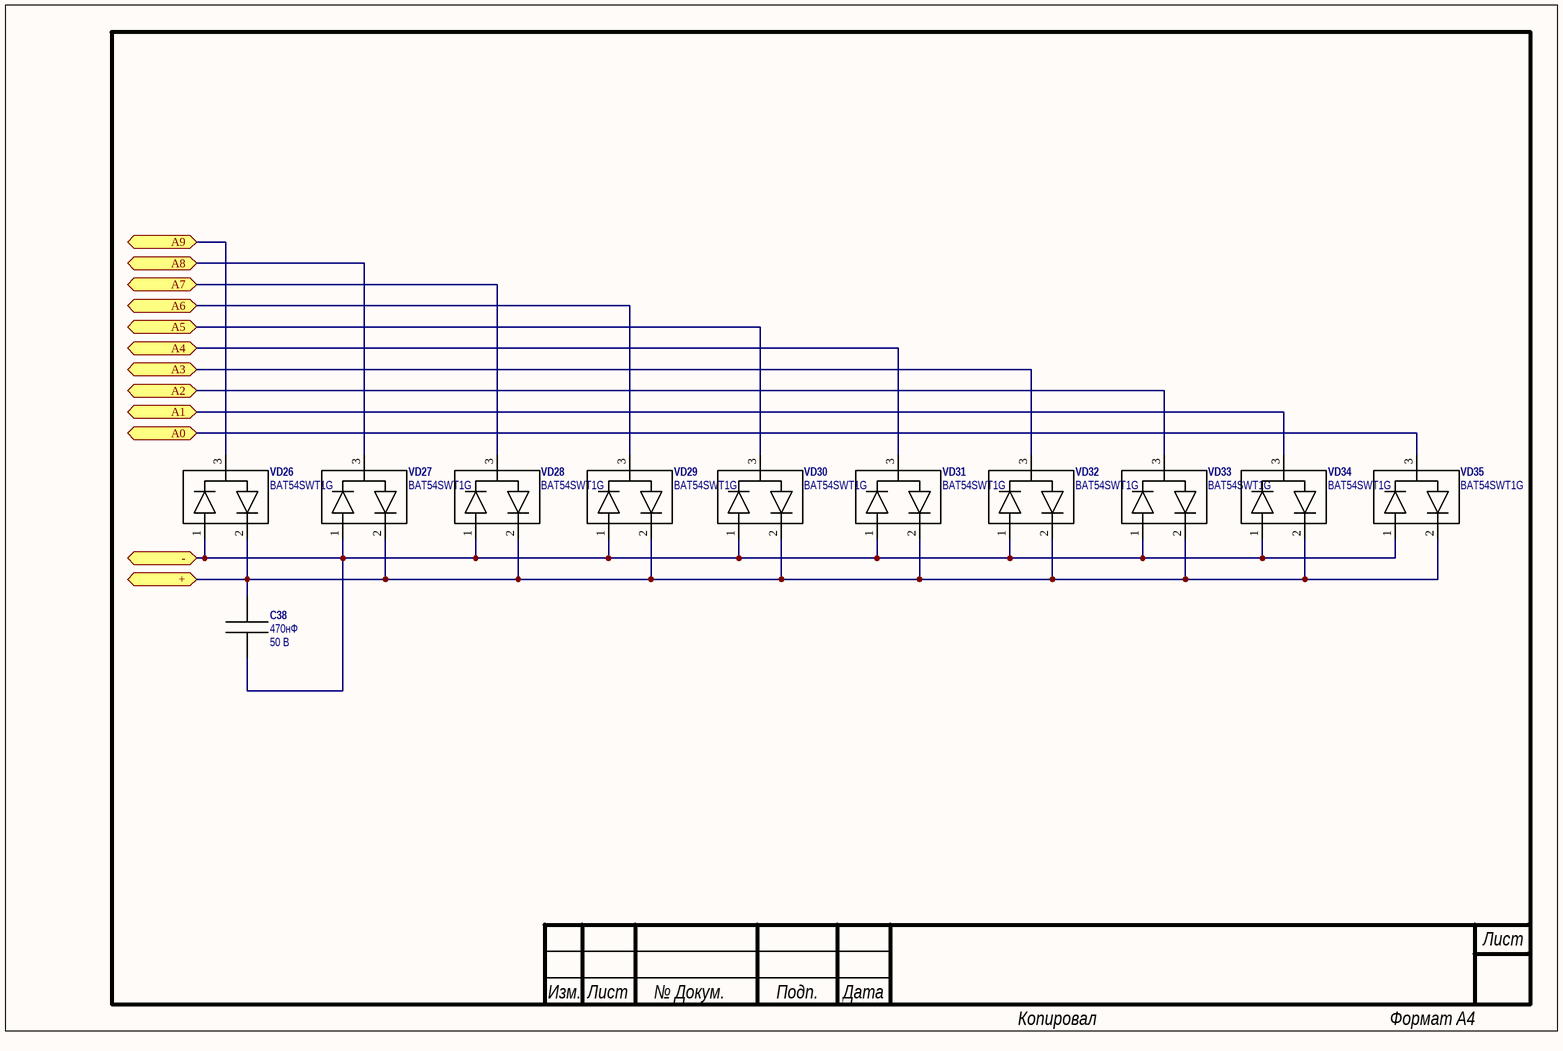
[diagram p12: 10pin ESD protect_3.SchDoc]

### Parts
C38  value 470нФ  VOLTAGE: 50 В  [C0805]  (hidden comment: 470нФ 10% 50 В)
VD26  BAT54SWT1G  [SC-70]
VD27  BAT54SWT1G  [SC-70]
VD28  BAT54SWT1G  [SC-70]
VD29  BAT54SWT1G  [SC-70]
VD30  BAT54SWT1G  [SC-70]
VD31  BAT54SWT1G  [SC-70]
VD32  BAT54SWT1G  [SC-70]
VD33  BAT54SWT1G  [SC-70]
VD34  BAT54SWT1G  [SC-70]
VD35  BAT54SWT1G  [SC-70]

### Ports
+, -, A0, A1, A2, A3, A4, A5, A6, A7, A8, A9

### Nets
+: C38.1 VD26.2 VD27.2 VD28.2 VD29.2 VD30.2 VD31.2 VD32.2 VD33.2 VD34.2 VD35.2 ; port +
-: C38.2 VD26.1 VD27.1 VD28.1 VD29.1 VD30.1 VD31.1 VD32.1 VD33.1 VD34.1 VD35.1 ; port -
A0: VD35.3 ; port A0
A1: VD34.3 ; port A1
A2: VD33.3 ; port A2
A3: VD32.3 ; port A3
A4: VD31.3 ; port A4
A5: VD30.3 ; port A5
A6: VD29.3 ; port A6
A7: VD28.3 ; port A7
A8: VD27.3 ; port A8
A9: VD26.3 ; port A9

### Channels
A/3: designators end in A; ports +=VIOA -=GND A0=A20 A1=A21 A2=A22 A3=A23 A4=A24 A5=A25 A6=A26 A7=A27 A8=A28 A9=A29
B/3: designators end in B; ports +=VIOB -=GND A0=B20 A1=B21 A2=B22 A3=B23 A4=B24 A5=B25 A6=B26 A7=B27 A8=B28 A9=B29

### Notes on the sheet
- Лист
- Изм.
- № Докум.
- Подп.
- Дата
- Копировал
- Формат
- А4

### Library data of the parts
C38 = 470нФ 50 В: as C64 on sheet 5A Stepdown 5V
VD26-VD35 = BAT54SWT1G: два диода Шоттки; articul: 1103

## Sheet 10pin ESD protect_4.SchDoc
size A4
Used 2 times, as channels A/4, B/4. Parts and nets are listed once, with the designators drawn on the sheet.
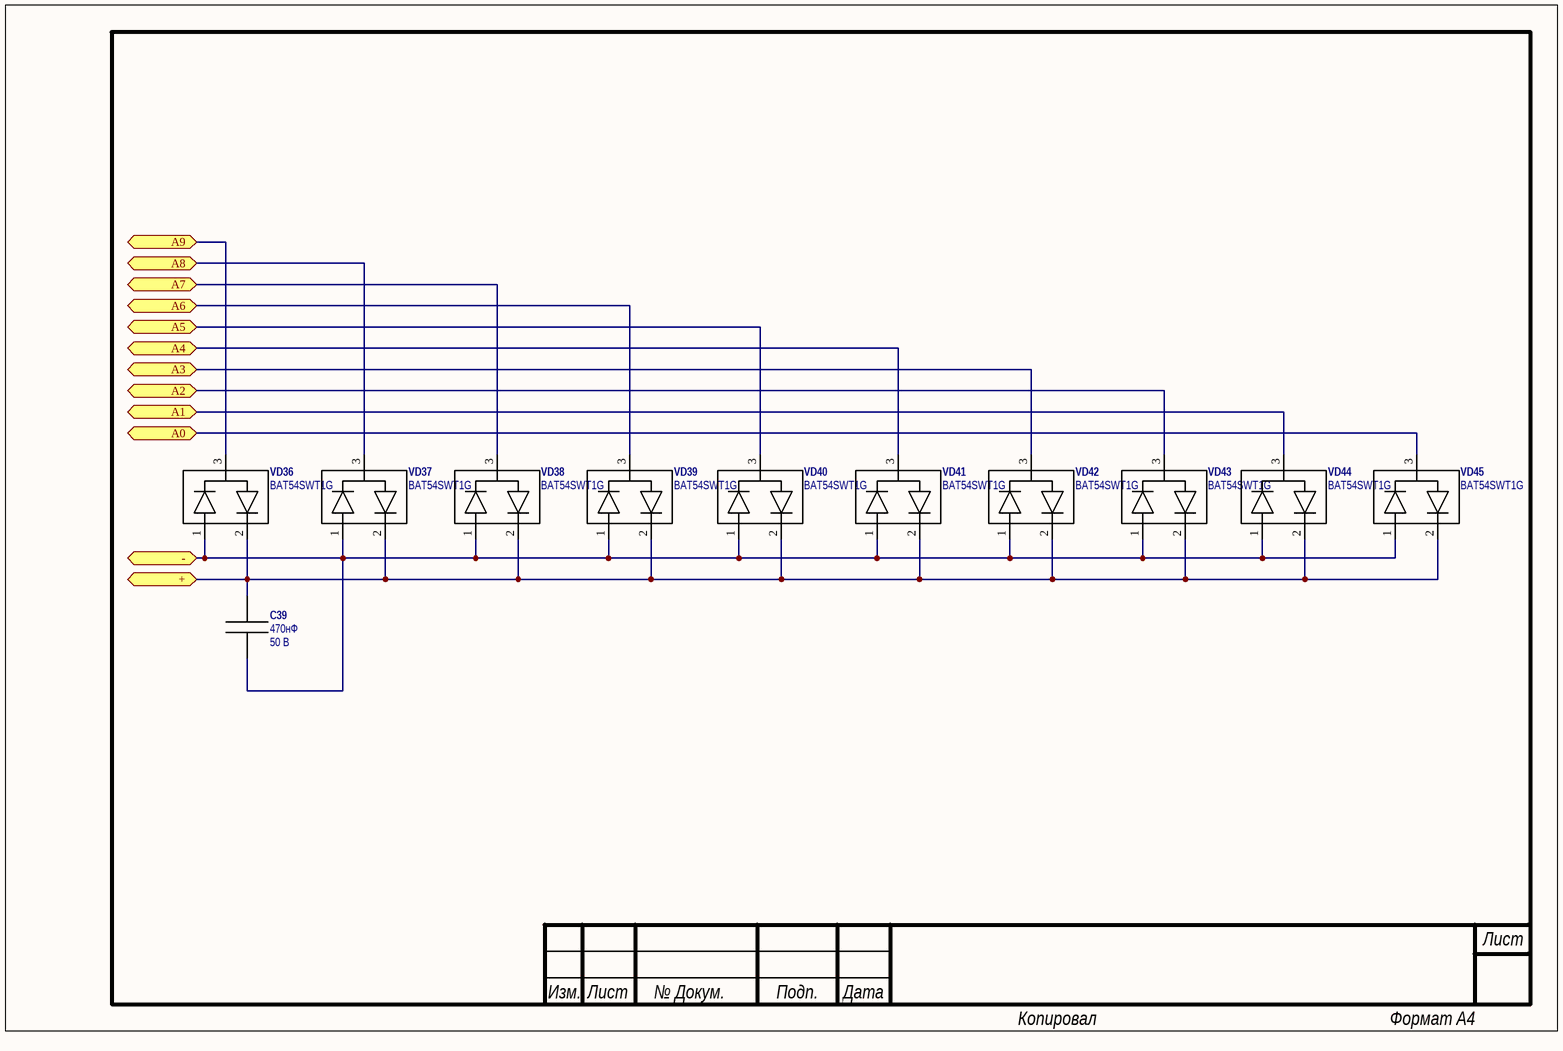
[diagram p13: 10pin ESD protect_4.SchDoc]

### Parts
C39  value 470нФ  VOLTAGE: 50 В  [C0805]  (hidden comment: 470нФ 10% 50 В)
VD36  BAT54SWT1G  [SC-70]
VD37  BAT54SWT1G  [SC-70]
VD38  BAT54SWT1G  [SC-70]
VD39  BAT54SWT1G  [SC-70]
VD40  BAT54SWT1G  [SC-70]
VD41  BAT54SWT1G  [SC-70]
VD42  BAT54SWT1G  [SC-70]
VD43  BAT54SWT1G  [SC-70]
VD44  BAT54SWT1G  [SC-70]
VD45  BAT54SWT1G  [SC-70]

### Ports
+, -, A0, A1, A2, A3, A4, A5, A6, A7, A8, A9

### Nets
+: C39.1 VD36.2 VD37.2 VD38.2 VD39.2 VD40.2 VD41.2 VD42.2 VD43.2 VD44.2 VD45.2 ; port +
-: C39.2 VD36.1 VD37.1 VD38.1 VD39.1 VD40.1 VD41.1 VD42.1 VD43.1 VD44.1 VD45.1 ; port -
A0: VD45.3 ; port A0
A1: VD44.3 ; port A1
A2: VD43.3 ; port A2
A3: VD42.3 ; port A3
A4: VD41.3 ; port A4
A5: VD40.3 ; port A5
A6: VD39.3 ; port A6
A7: VD38.3 ; port A7
A8: VD37.3 ; port A8
A9: VD36.3 ; port A9

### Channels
A/4: designators end in A; ports +=VIOA -=GND A0=A30 A1=A31 A2=A32 A3=A33 A4=A34 A5=A35 A6=A36 A7=A37 A8=A38 A9=A39
B/4: designators end in B; ports +=VIOB -=GND A0=B30 A1=B31 A2=B32 A3=B33 A4=B34 A5=B35 A6=B36 A7=B37 A8=B38 A9=B39

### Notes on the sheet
- Лист
- Изм.
- № Докум.
- Подп.
- Дата
- Копировал
- Формат
- А4

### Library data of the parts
C39 = 470нФ 50 В: as C64 on sheet 5A Stepdown 5V
VD36-VD45 = BAT54SWT1G: два диода Шоттки; articul: 1103

## Sheet 10pin ESD protect_6.SchDoc
size A4
Used 2 times, as channels A/6, B/6. Parts and nets are listed once, with the designators drawn on the sheet.
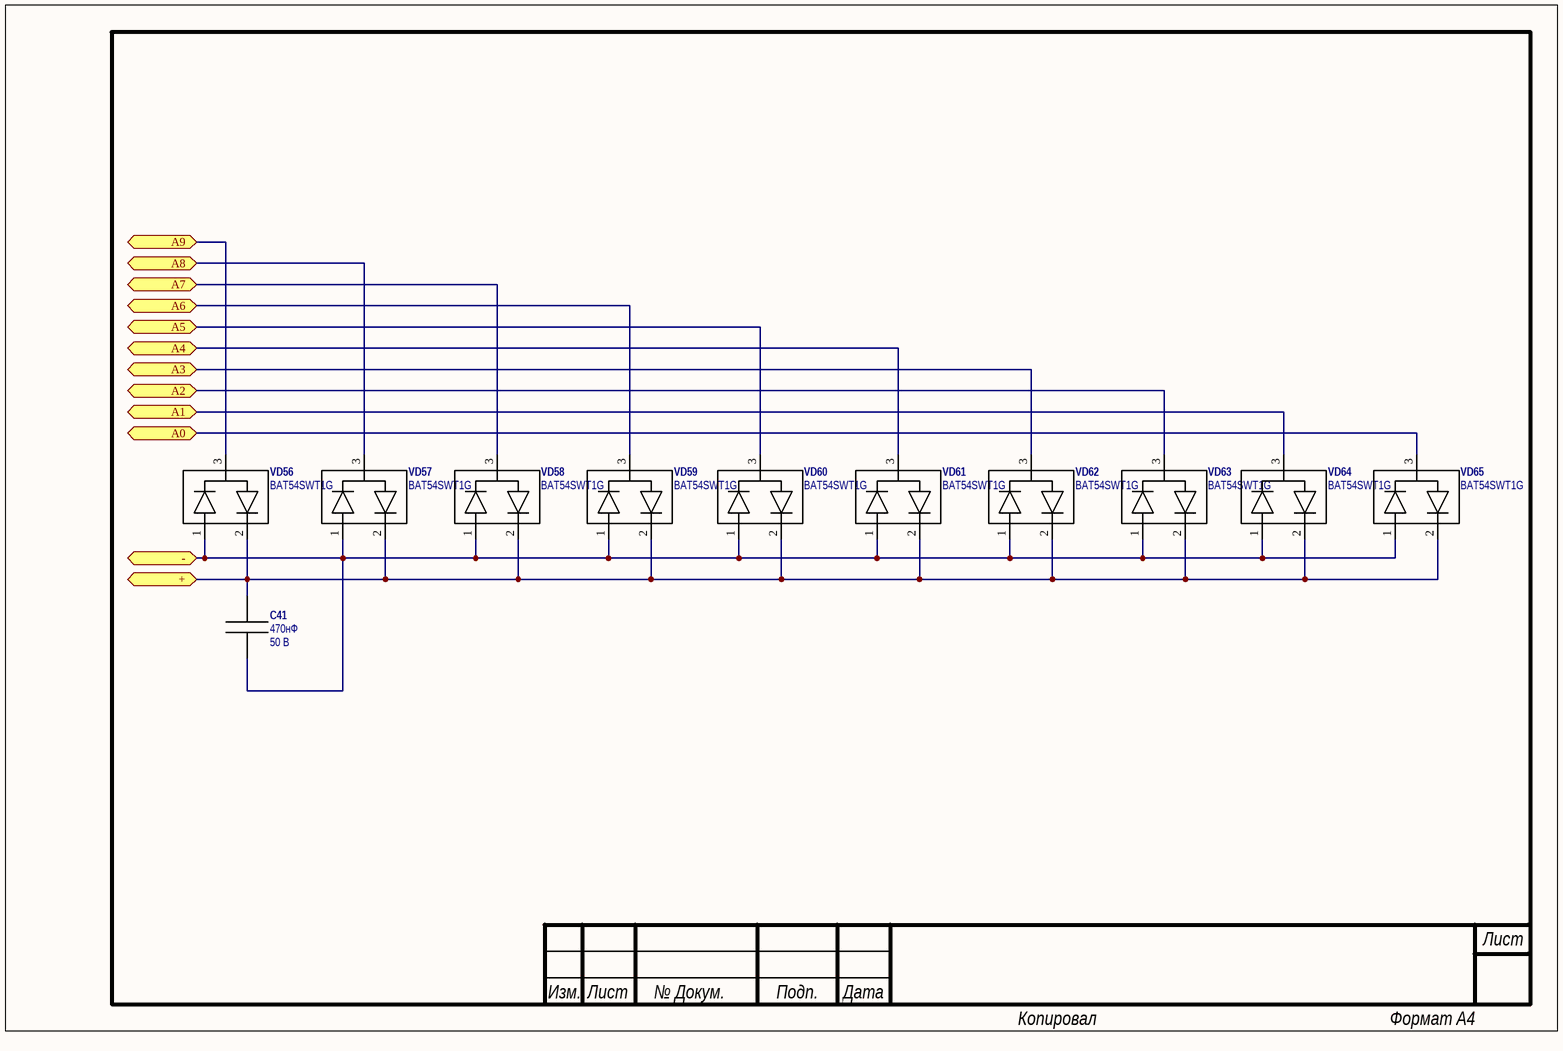
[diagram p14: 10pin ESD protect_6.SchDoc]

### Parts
C41  value 470нФ  VOLTAGE: 50 В  [C0805]  (hidden comment: 470нФ 10% 50 В)
VD56  BAT54SWT1G  [SC-70]
VD57  BAT54SWT1G  [SC-70]
VD58  BAT54SWT1G  [SC-70]
VD59  BAT54SWT1G  [SC-70]
VD60  BAT54SWT1G  [SC-70]
VD61  BAT54SWT1G  [SC-70]
VD62  BAT54SWT1G  [SC-70]
VD63  BAT54SWT1G  [SC-70]
VD64  BAT54SWT1G  [SC-70]
VD65  BAT54SWT1G  [SC-70]

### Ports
+, -, A0, A1, A2, A3, A4, A5, A6, A7, A8, A9

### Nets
+: C41.1 VD56.2 VD57.2 VD58.2 VD59.2 VD60.2 VD61.2 VD62.2 VD63.2 VD64.2 VD65.2 ; port +
-: C41.2 VD56.1 VD57.1 VD58.1 VD59.1 VD60.1 VD61.1 VD62.1 VD63.1 VD64.1 VD65.1 ; port -
A0: VD65.3 ; port A0
A1: VD64.3 ; port A1
A2: VD63.3 ; port A2
A3: VD62.3 ; port A3
A4: VD61.3 ; port A4
A5: VD60.3 ; port A5
A6: VD59.3 ; port A6
A7: VD58.3 ; port A7
A8: VD57.3 ; port A8
A9: VD56.3 ; port A9

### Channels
A/6: designators end in A; ports +=VIOA -=GND A0=A50 A1=A51 A2=A52 A3=A53 A4=A54 A5=A55 A6=A56 A7=A57 A8=A58 A9=A59
B/6: designators end in B; ports +=VIOB -=GND A0=B50 A1=B51 A2=B52 A3=B53 A4=B54 A5=B55 A6=B56 A7=B57 A8=B58 A9=B59

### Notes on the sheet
- Лист
- Изм.
- № Докум.
- Подп.
- Дата
- Копировал
- Формат
- А4

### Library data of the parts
C41 = 470нФ 50 В: as C64 on sheet 5A Stepdown 5V
VD56-VD65 = BAT54SWT1G: два диода Шоттки; articul: 1103

## Sheet 10pin ESD protect_5.SchDoc
size A4
Used 2 times, as channels A/5, B/5. Parts and nets are listed once, with the designators drawn on the sheet.
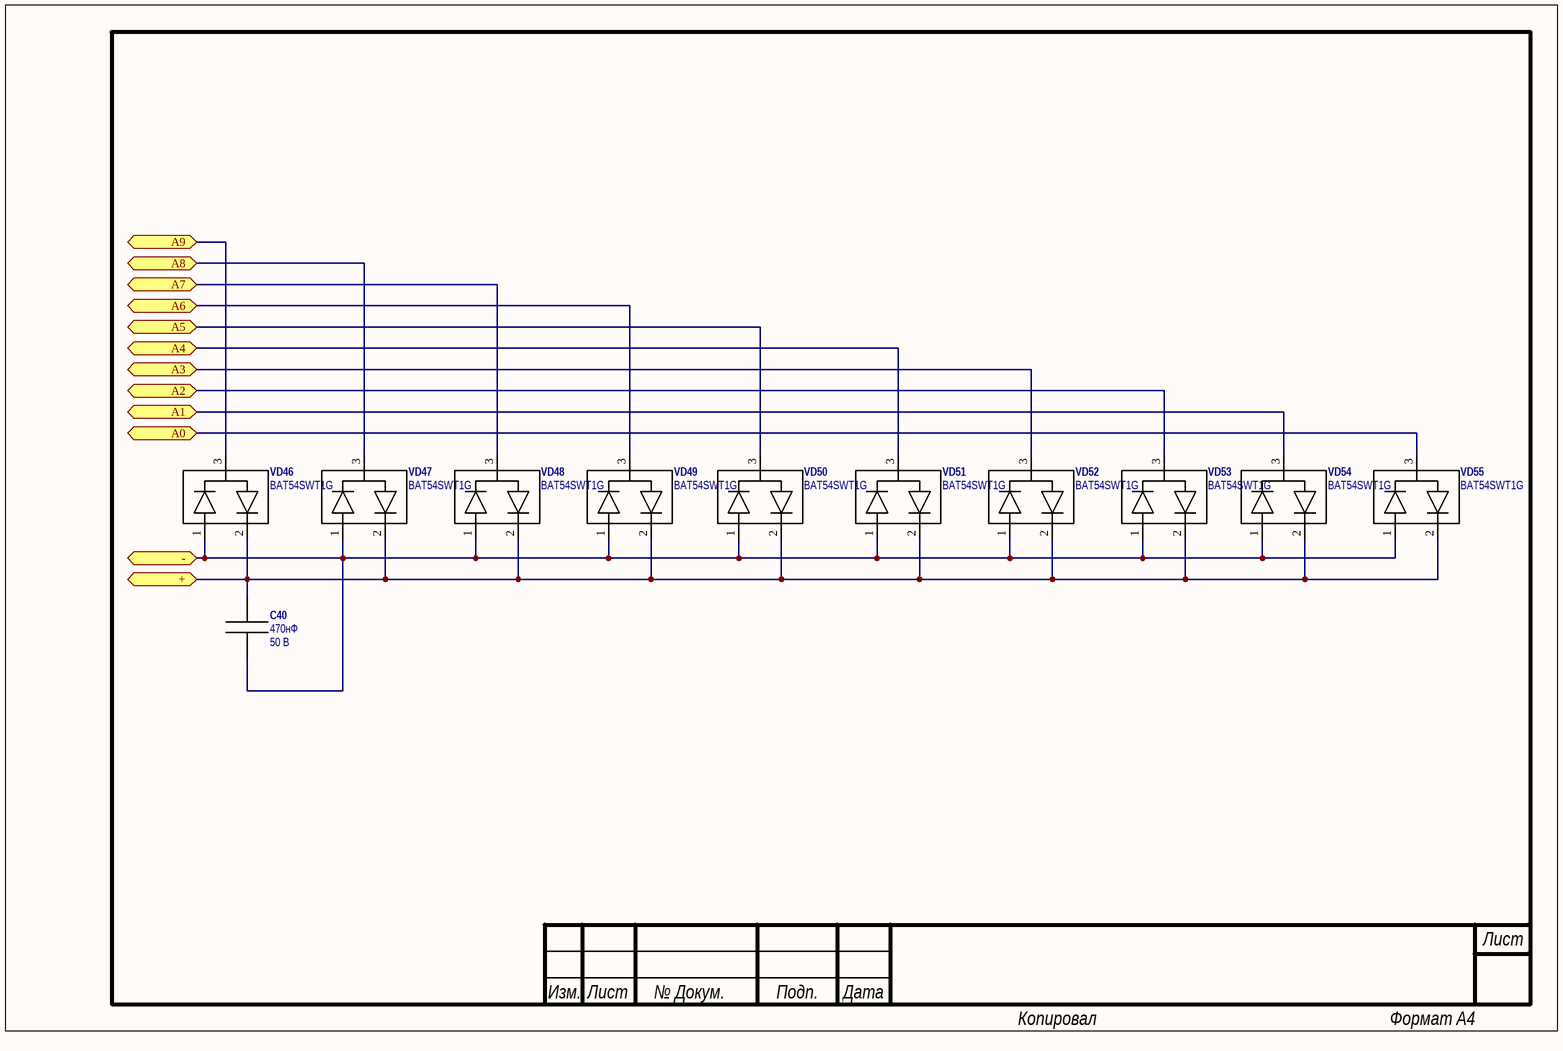
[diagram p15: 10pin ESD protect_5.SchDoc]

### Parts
C40  value 470нФ  VOLTAGE: 50 В  [C0805]  (hidden comment: 470нФ 10% 50 В)
VD46  BAT54SWT1G  [SC-70]
VD47  BAT54SWT1G  [SC-70]
VD48  BAT54SWT1G  [SC-70]
VD49  BAT54SWT1G  [SC-70]
VD50  BAT54SWT1G  [SC-70]
VD51  BAT54SWT1G  [SC-70]
VD52  BAT54SWT1G  [SC-70]
VD53  BAT54SWT1G  [SC-70]
VD54  BAT54SWT1G  [SC-70]
VD55  BAT54SWT1G  [SC-70]

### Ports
+, -, A0, A1, A2, A3, A4, A5, A6, A7, A8, A9

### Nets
+: C40.1 VD46.2 VD47.2 VD48.2 VD49.2 VD50.2 VD51.2 VD52.2 VD53.2 VD54.2 VD55.2 ; port +
-: C40.2 VD46.1 VD47.1 VD48.1 VD49.1 VD50.1 VD51.1 VD52.1 VD53.1 VD54.1 VD55.1 ; port -
A0: VD55.3 ; port A0
A1: VD54.3 ; port A1
A2: VD53.3 ; port A2
A3: VD52.3 ; port A3
A4: VD51.3 ; port A4
A5: VD50.3 ; port A5
A6: VD49.3 ; port A6
A7: VD48.3 ; port A7
A8: VD47.3 ; port A8
A9: VD46.3 ; port A9

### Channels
A/5: designators end in A; ports +=VIOA -=GND A0=A40 A1=A41 A2=A42 A3=A43 A4=A44 A5=A45 A6=A46 A7=A47 A8=A48 A9=A49
B/5: designators end in B; ports +=VIOB -=GND A0=B40 A1=B41 A2=B42 A3=B43 A4=B44 A5=B45 A6=B46 A7=B47 A8=B48 A9=B49

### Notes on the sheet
- Лист
- Изм.
- № Докум.
- Подп.
- Дата
- Копировал
- Формат
- А4

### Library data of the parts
C40 = 470нФ 50 В: as C64 on sheet 5A Stepdown 5V
VD46-VD55 = BAT54SWT1G: два диода Шоттки; articul: 1103

## Sheet B_PLD-80_IO.SchDoc
size custom portrait
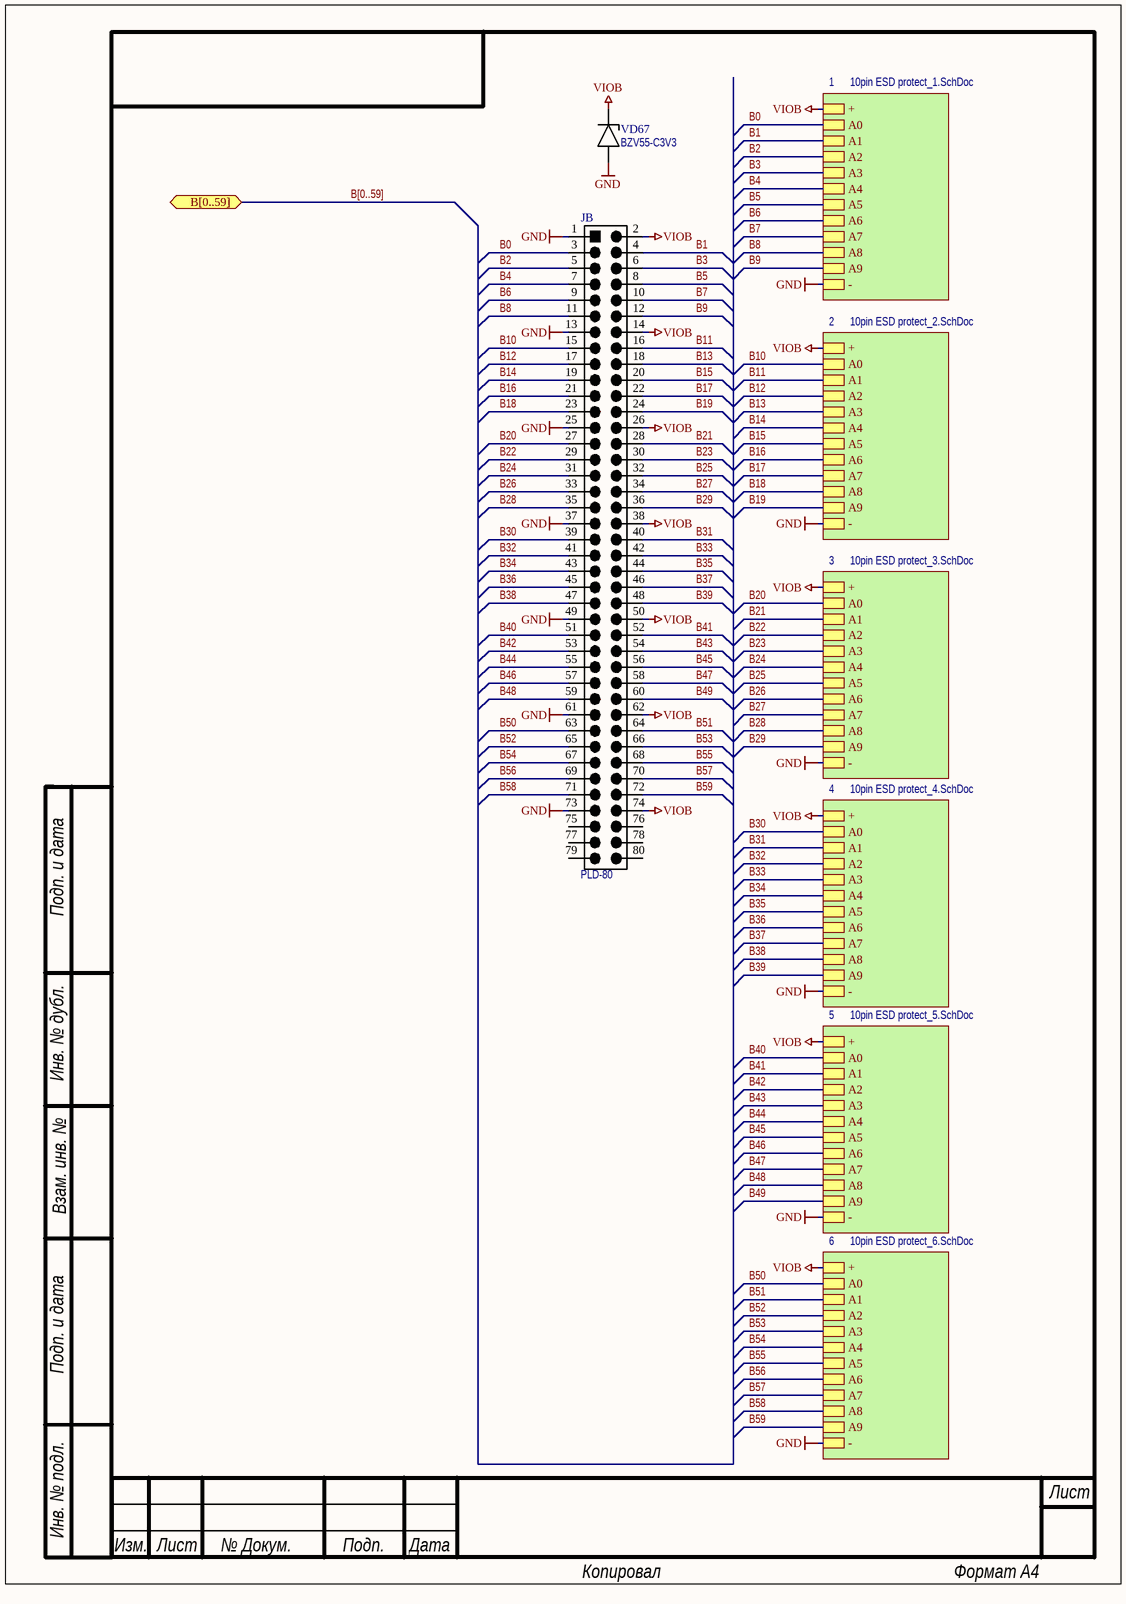
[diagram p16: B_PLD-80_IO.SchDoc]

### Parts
JB  PLD-80  [HEADER 2X40]
VD67  BZV55-C3V3  [SOD-80]

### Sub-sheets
1 = 10pin ESD protect_1.SchDoc: A0, A1, A2, A3, A4, A5, A6, A7, A8, A9, -, +
2 = 10pin ESD protect_2.SchDoc: A0, A1, A2, A3, A4, A5, A6, A7, A8, A9, -, +
3 = 10pin ESD protect_3.SchDoc: A0, A1, A2, A3, A4, A5, A6, A7, A8, A9, -, +
4 = 10pin ESD protect_4.SchDoc: A0, A1, A2, A3, A4, A5, A6, A7, A8, A9, -, +
5 = 10pin ESD protect_5.SchDoc: A0, A1, A2, A3, A4, A5, A6, A7, A8, A9, -, +
6 = 10pin ESD protect_6.SchDoc: A0, A1, A2, A3, A4, A5, A6, A7, A8, A9, -, +

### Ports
B[0..59]

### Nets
GND: JB.1 JB.13 JB.25 JB.37 JB.49 JB.61 JB.73 VD67.1 ; sheet 1/-, sheet 2/-, sheet 3/-, sheet 4/-, sheet 6/-, sheet 5/-
VIOB: JB.2 JB.14 JB.26 JB.38 JB.50 JB.62 JB.74 VD67.2 ; sheet 1/+, sheet 2/+, sheet 3/+, sheet 4/+, sheet 6/+, sheet 5/+
B0: JB.3 ; sheet 1/A0
B1: JB.4 ; sheet 1/A1
B2: JB.5 ; sheet 1/A2
B3: JB.6 ; sheet 1/A3
B4: JB.7 ; sheet 1/A4
B5: JB.8 ; sheet 1/A5
B6: JB.9 ; sheet 1/A6
B7: JB.10 ; sheet 1/A7
B8: JB.11 ; sheet 1/A8
B9: JB.12 ; sheet 1/A9
B10: JB.15 ; sheet 2/A0
B11: JB.16 ; sheet 2/A1
B12: JB.17 ; sheet 2/A2
B13: JB.18 ; sheet 2/A3
B14: JB.19 ; sheet 2/A4
B15: JB.20 ; sheet 2/A5
B16: JB.21 ; sheet 2/A6
B17: JB.22 ; sheet 2/A7
B18: JB.23 ; sheet 2/A8
B19: JB.24 ; sheet 2/A9
B20: JB.27 ; sheet 3/A0
B21: JB.28 ; sheet 3/A1
B22: JB.29 ; sheet 3/A2
B23: JB.30 ; sheet 3/A3
B24: JB.31 ; sheet 3/A4
B25: JB.32 ; sheet 3/A5
B26: JB.33 ; sheet 3/A6
B27: JB.34 ; sheet 3/A7
B28: JB.35 ; sheet 3/A8
B29: JB.36 ; sheet 3/A9
B30: JB.39 ; sheet 4/A0
B31: JB.40 ; sheet 4/A1
B32: JB.41 ; sheet 4/A2
B33: JB.42 ; sheet 4/A3
B34: JB.43 ; sheet 4/A4
B35: JB.44 ; sheet 4/A5
B36: JB.45 ; sheet 4/A6
B37: JB.46 ; sheet 4/A7
B38: JB.47 ; sheet 4/A8
B39: JB.48 ; sheet 4/A9
B40: JB.51 ; sheet 5/A0
B41: JB.52 ; sheet 5/A1
B42: JB.53 ; sheet 5/A2
B43: JB.54 ; sheet 5/A3
B44: JB.55 ; sheet 5/A4
B45: JB.56 ; sheet 5/A5
B46: JB.57 ; sheet 5/A6
B47: JB.58 ; sheet 5/A7
B48: JB.59 ; sheet 5/A8
B49: JB.60 ; sheet 5/A9
B50: JB.63 ; sheet 6/A0
B51: JB.64 ; sheet 6/A1
B52: JB.65 ; sheet 6/A2
B53: JB.66 ; sheet 6/A3
B54: JB.67 ; sheet 6/A4
B55: JB.68 ; sheet 6/A5
B56: JB.69 ; sheet 6/A6
B57: JB.70 ; sheet 6/A7
B58: JB.71 ; sheet 6/A8
B59: JB.72 ; sheet 6/A9

Not connected (* = marked no-connect by the designer): JB 75 76 77 78 79 80

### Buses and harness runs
bus B[0..59] = port B[0..59]

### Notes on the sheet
- Подп. и дата
- Инв. № дубл.
- Взам. инв. №
- Инв. № подл.
- Лист
- Изм.
- № Докум.
- Подп.
- Дата
- Копировал
- Формат
- А4

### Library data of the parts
JB = PLD-80: Штырьки на плату шаг 2,54 мм
VD67 = BZV55-C3V3: as VD66 on sheet A_PLD-80_IO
